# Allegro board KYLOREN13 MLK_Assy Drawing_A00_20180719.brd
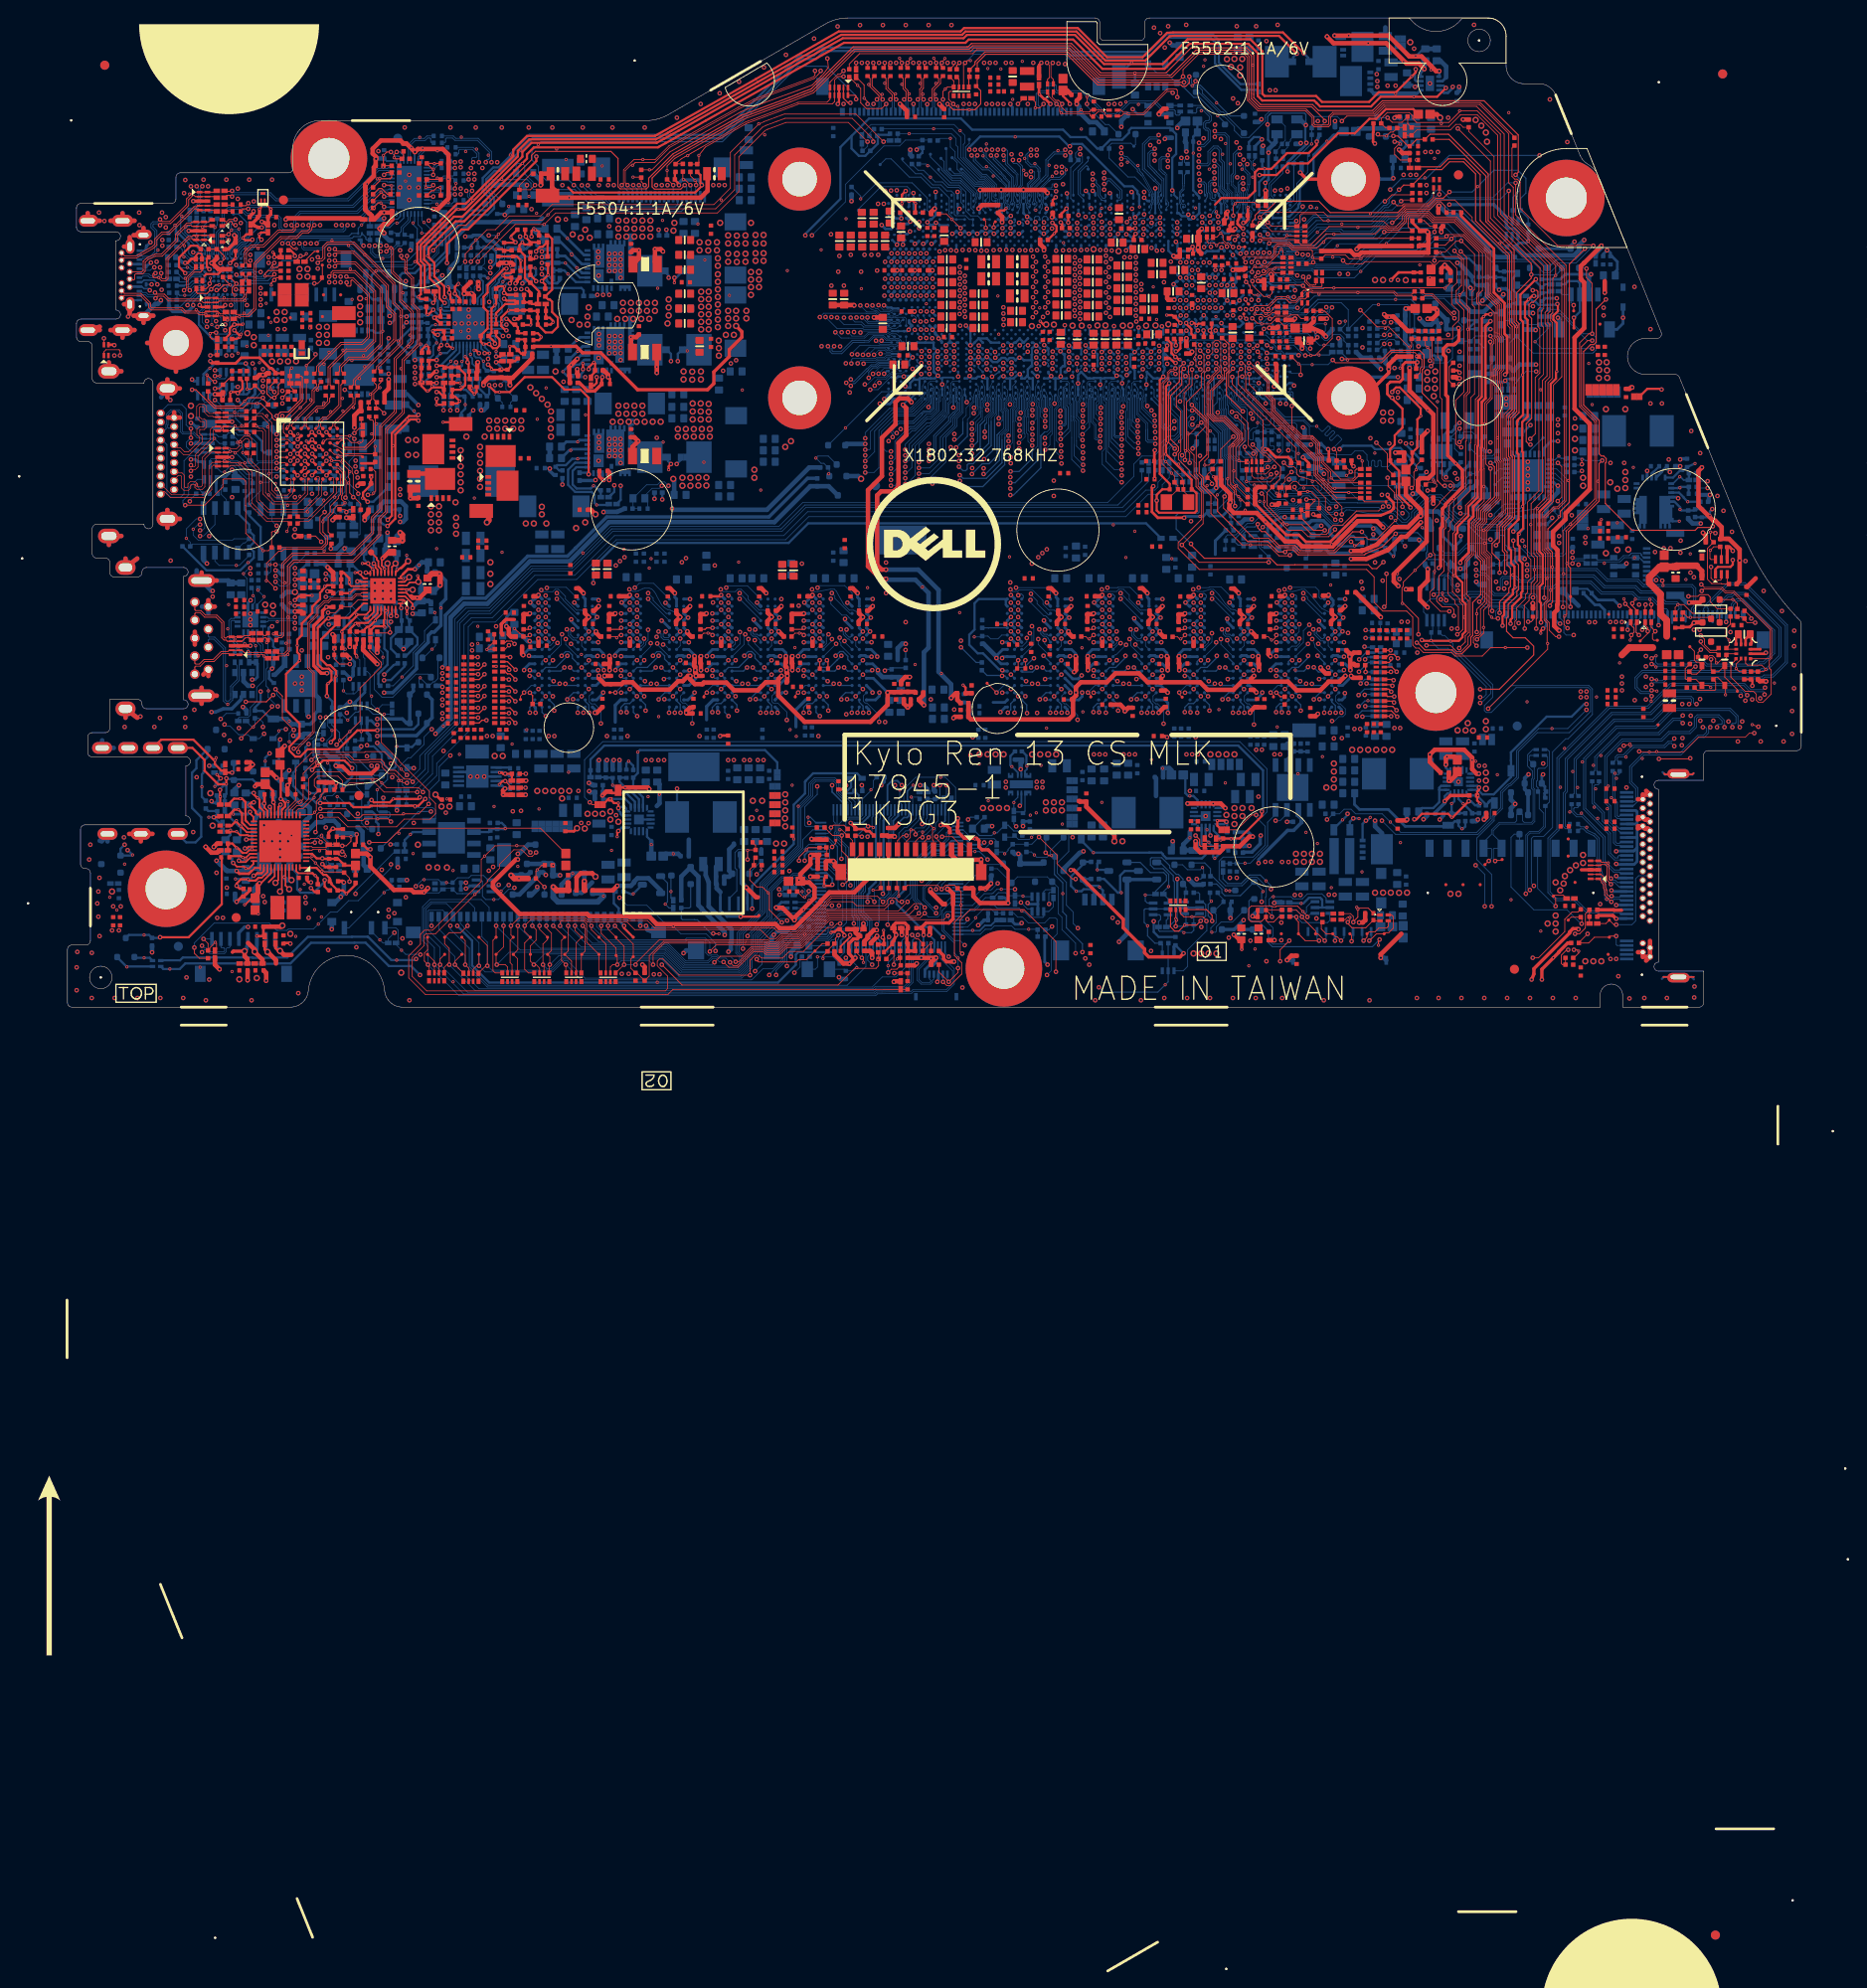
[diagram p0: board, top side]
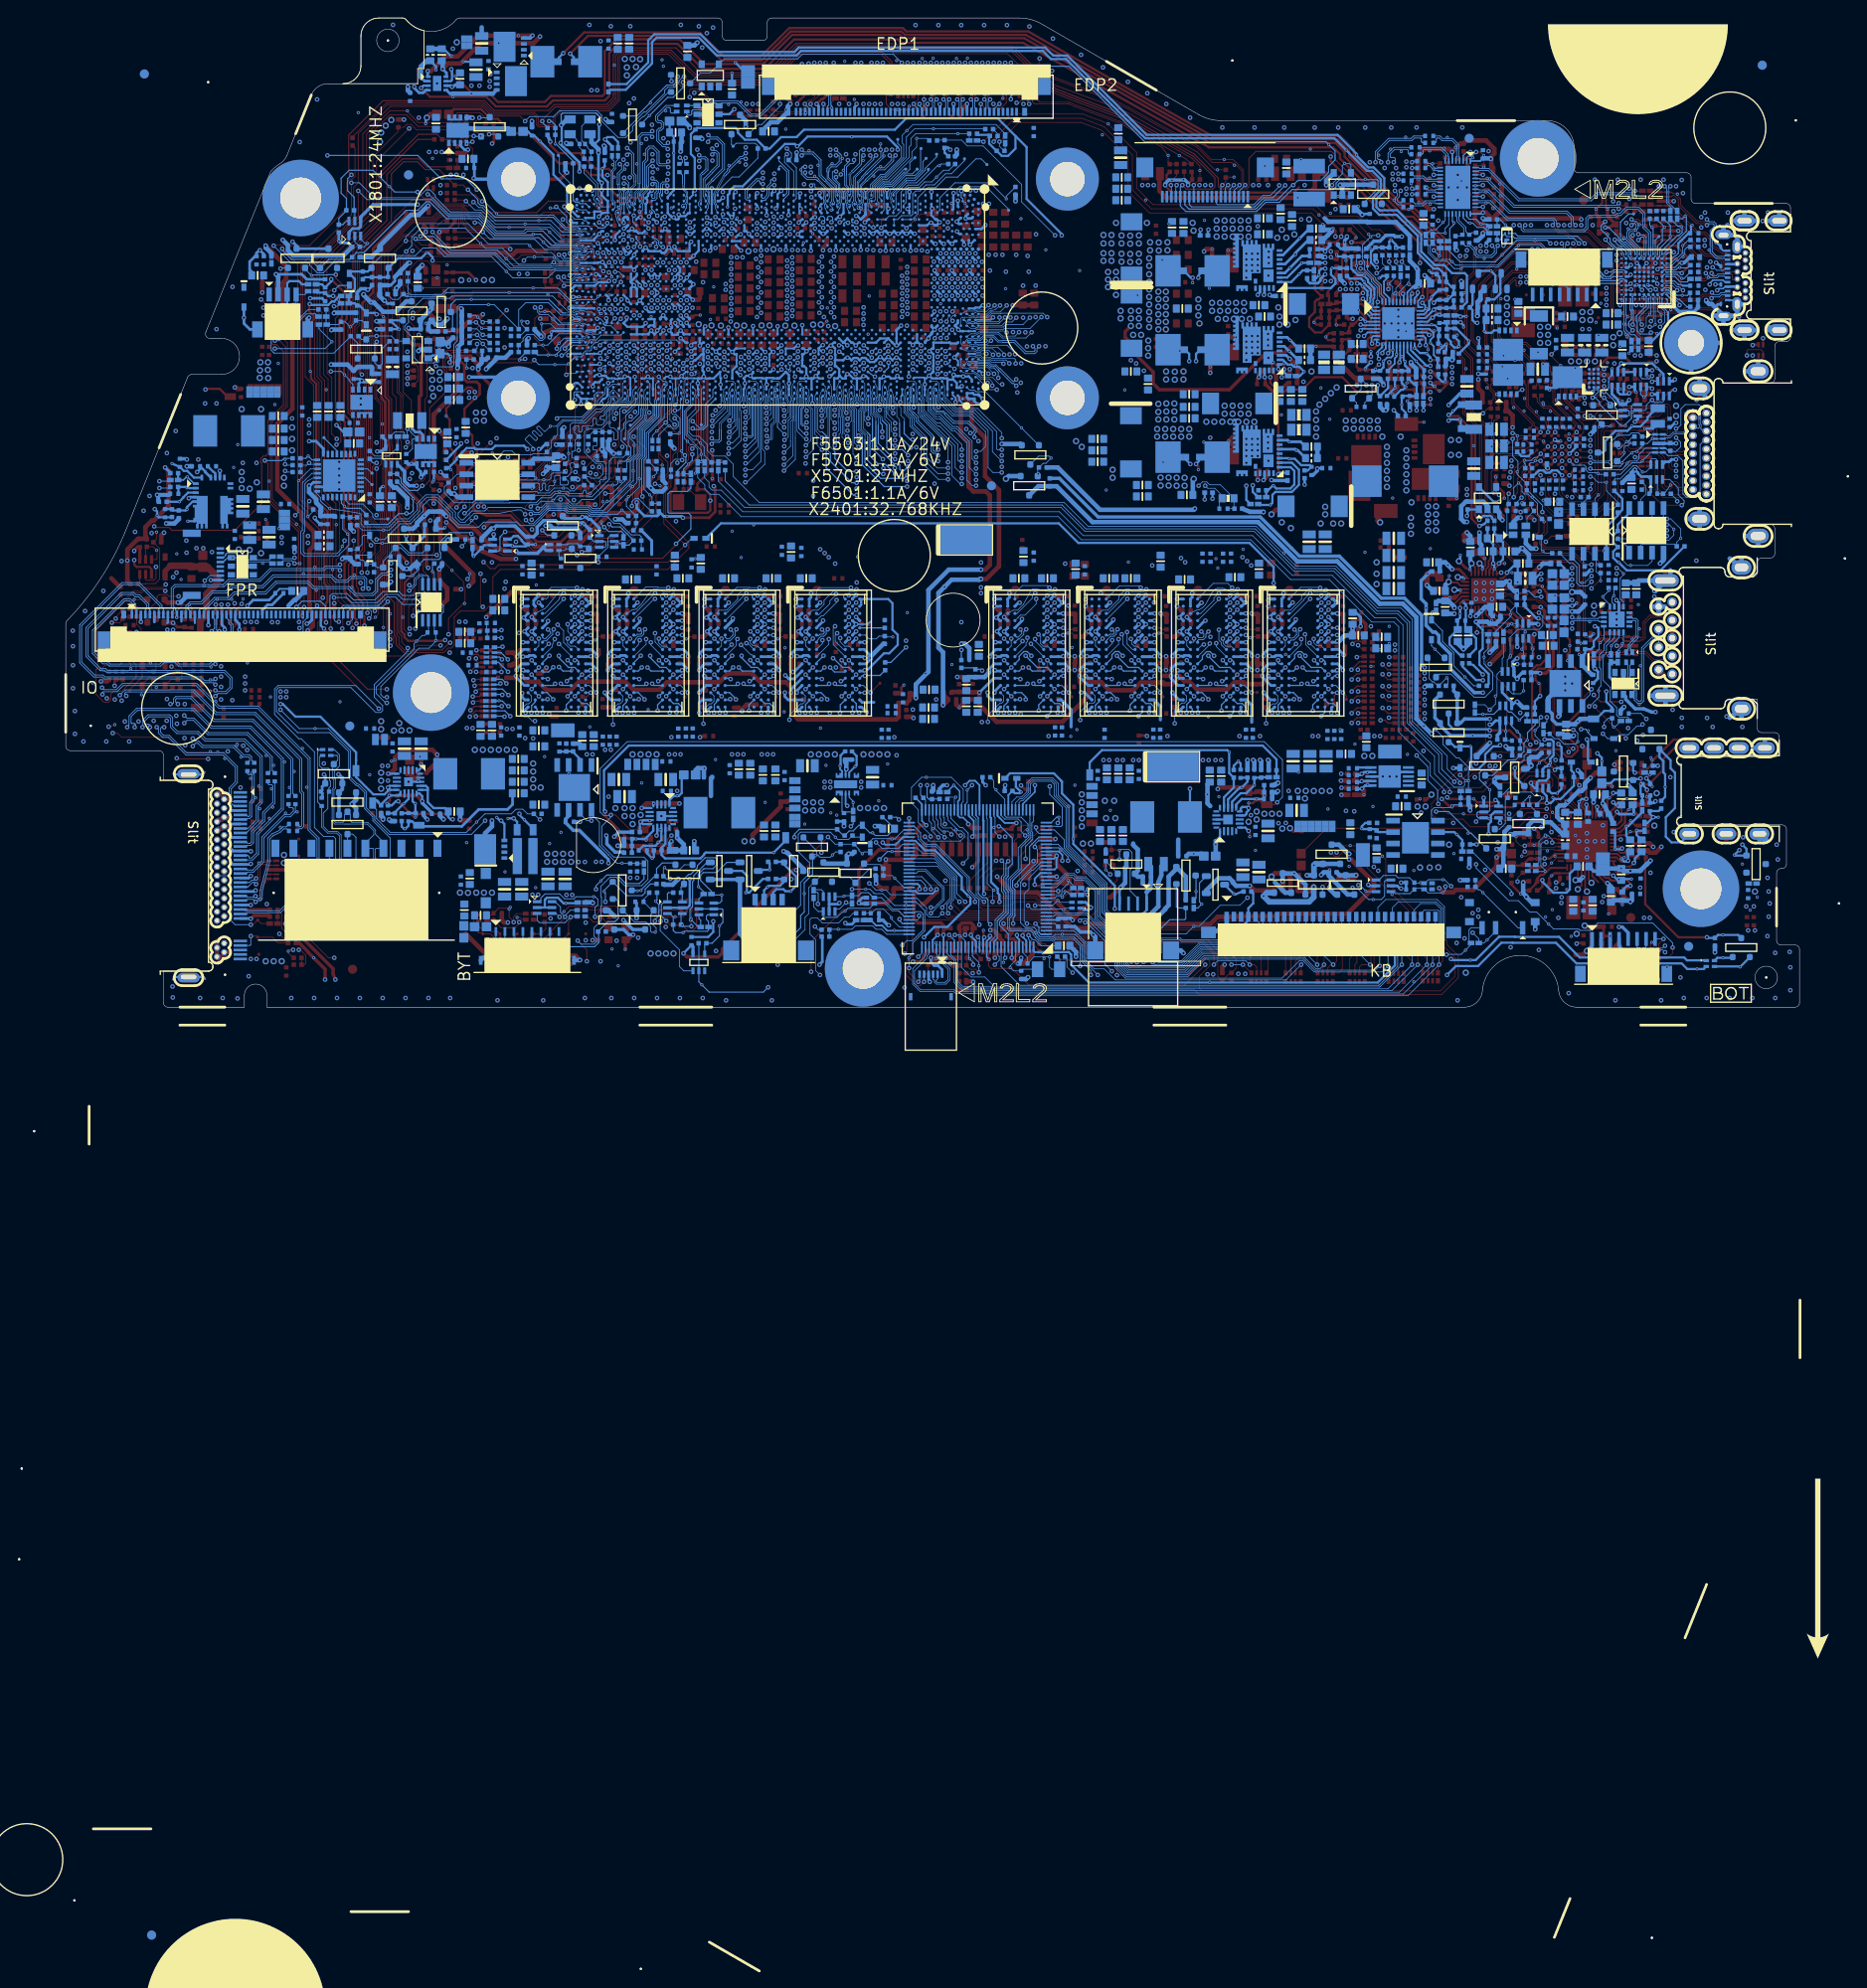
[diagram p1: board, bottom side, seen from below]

Outline 192.65 x 109.9 mm; copper layers: TOP, L2SGND, L3SGND, L4SGND, L5GND, L6, L7GND, BOTTOM. Coordinates in mm from the lower left corner of the outline.

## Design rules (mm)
constraint set DEFAULT: min track width 0.127, pair gap 0.102
net group CNV: nets CNV_RGI_DT CNV_WT_RCOMP
net group CPU_50: nets PROCHOT PROCHOT#_CPU
net group DDR4_4MIL: nets M_A_CLK M_B_CLK
net group DDR4_CKE_40-MW: nets M_A_CKE0 M_B_CKE0
net group DDR4_REST: nets SM_DRAMRST# SM_DRAMRST#_CPU
net group GND: nets EC_AGND MIC_GND
net group PAIR_CPU_DP1_CTRL_SMB-DIFF1: nets CPU_DP1_CTRL_CLK CPU_DP1_CTRL_DATA
net group PAIR_CPU_DP2_CTRL_SMB-DIFF1: nets CPU_DP2_CTRL_CLK CPU_DP2_CTRL_DATA
net group PAIR_CPU_I2C_TP-DIFF1: nets CPU_I2C_SCL_TP CPU_I2C_SDA_TP
net group PAIR_CPU_I2C_TS-DIFF1: nets CPU_I2C_SCL_TS CPU_I2C_SDA_TS
net group PAIR_CPU_SMB_THM-DIFF1: nets CPU_SMB_SCL_THM CPU_SMB_SDA_THM
net group PAIR_DMIC_CODEC_R-DIFF1: nets DMIC_SCL_CODEC_R DMIC_SDA_CODEC_R
net group PAIR_HDMI_SMB_CON-DIFF1: nets HDMI_SCL_CON HDMI_SDA_CON
net group PAIR_HDMI_SMB_R-DIFF1: nets HDMI_SCL_R HDMI_SDA_R
net group PAIR_I2C_PD_MUX-DIFF1: nets I2C_CLK_PD_MUX I2C_DATA_PD_MUX
net group PAIR_ICSP-DIFF1: nets ICSP_CLK ICSP_DAT
net group PAIR_KBC_PS2_I2C_TP-DIFF1: nets KBC_PS2_SCL_TP KBC_PS2_SDA_TP
net group PAIR_PCIE_RCOMP-DIFF1: nets PCIE_RCOMPN PCIE_RCOMPP
net group PAIR_PS175_SMB-DIFF1: nets PS175_CSCL PS175_CSDA
net group PAIR_SPK_I2C_CODEC-DIFF1: nets SPK_SCL_CODEC SPK_SDA_CODEC
net group PAIR_TYPEC_SMB-DIFF1: nets TYPEC_SMBCLK TYPEC_SMBDA
net group PAIR_TYPEC_SMB_Q-DIFF1: nets TYPEC_SMBCLK_Q TYPEC_SMBDA_Q
net group PAIR_VCORE_SENSE-DIFF1: nets VCCCORE_SENSE VSSCORE_SENSE
net group PAIR_VGT_SENSE-DIFF1: nets VCCGT_SENSE VSSGT_SENSE
net group PAIR_VSA_SENSE-DIFF1: nets VCCSA_SENSE VSSSA_SENSE
net group R72_16_M_A_CLK0-DIFF1: nets M_A_CLK0 M_A_CLK#0
net group R72_16_M_B_CLK0-DIFF1: nets M_B_CLK0 M_B_CLK#0
net group R85_12_USB1_USB30_RX-DIFF1: nets USB1_USB30_RX_N USB1_USB30_RX_P
net group R85_12_USB1_USB30_TX-DIFF1: nets USB1_USB30_TX_N USB1_USB30_TX_P
net group R85_15_CCD_USB20-DIFF1: nets CCD_USB20_N CCD_USB20_P
net group R85_15_CCD_USB20_CON-DIFF1: nets CCD_USB20_CON_N CCD_USB20_CON_P
net group R85_15_DP2_AUX_C2-DIFF1: nets DP2_AUX_C2_N DP2_AUX_C2_P
net group R85_15_TBTA_SENSE-DIFF1: nets TBTA_SENSEN TBTA_SENSEP
net group R85_15_USB2_USB20-DIFF1: nets USB2_USB20_N USB2_USB20_P
net group R85_15_USB4_USB20-DIFF1: nets USB4_USB20_N USB4_USB20_P
net group R85_15_WLAN_PCIE_RX-DIFF1: nets WLAN_PCIE_RX_N WLAN_PCIE_RX_P
net group R85_16_M_A_DQS0-DIFF1: nets M_A_DQS_DN0 M_A_DQS_DP0
net group R85_16_M_A_DQS1-DIFF1: nets M_A_DQS_DN1 M_A_DQS_DP1
net group R85_16_M_A_DQS2-DIFF1: nets M_A_DQS_DN2 M_A_DQS_DP2
net group R85_16_M_A_DQS3-DIFF1: nets M_A_DQS_DN3 M_A_DQS_DP3
net group R85_16_M_A_DQS4-DIFF1: nets M_A_DQS_DN4 M_A_DQS_DP4
net group R85_16_M_A_DQS5-DIFF1: nets M_A_DQS_DN5 M_A_DQS_DP5
net group R85_16_M_A_DQS6-DIFF1: nets M_A_DQS_DN6 M_A_DQS_DP6
net group R85_16_M_A_DQS7-DIFF1: nets M_A_DQS_DN7 M_A_DQS_DP7
net group R85_16_M_B_DQS0-DIFF1: nets M_B_DQS_DN0 M_B_DQS_DP0
net group R85_16_M_B_DQS1-DIFF1: nets M_B_DQS_DN1 M_B_DQS_DP1
net group R85_16_M_B_DQS2-DIFF1: nets M_B_DQS_DN2 M_B_DQS_DP2
net group R85_16_M_B_DQS3-DIFF1: nets M_B_DQS_DN3 M_B_DQS_DP3
net group R85_16_M_B_DQS4-DIFF1: nets M_B_DQS_DN4 M_B_DQS_DP4
net group R85_16_M_B_DQS5-DIFF1: nets M_B_DQS_DN5 M_B_DQS_DP5
net group R85_16_M_B_DQS6-DIFF1: nets M_B_DQS_DN6 M_B_DQS_DP6
net group R85_16_M_B_DQS7-DIFF1: nets M_B_DQS_DN7 M_B_DQS_DP7
net group SPI_CLK_50: nets SPI_CLK_HDMI SPI_CLK_PD
net group T8: nets CMP_VIN0_R VD_IN1_C
net group TESTPD_4MIL: nets CPU_D4_TP CPU_D6_TP
net group TPM_5MIL: nets TPM_GPIO0 TPM_GPIO4
net group USB_OC: nets USB_OC0# USB_OC1#
net group XTAL-MW: nets MEC_XTAL1_R MEC_XTAL2
net group 65982DC: nets 65982D_DBG_CTL1 65982D_DBG_CTL2 65982D_DEBUG1 65982D_DEBUG2 65982D_DIG_AUD_N 65982D_DIG_AUD_P 65982D_GPIO2 65982D_GPIO3 65982D_GPIO5 65982D_GPIO8 65982D_HPD_CON 65982D_HRESET 65982D_I2C_ADDR 65982D_LSRX 65982D_LSTX 65982D_MRESET 65982D_RESET_N 65982D_ROSC 65982D_SBU1_R 65982D_SBU2_R 65982D_UART_RX CAD_SNK DP1_HPD_CPU DP1_HPD_CPU_R DPEQ0_A1 DPEQ1 EQ0 EQ1 HPDIN I2CEN LPS_SW LPS_SW_A LPS_SW_B LPS_SW_C LPS_SW_D MUX_HPD_CON PD_IRQ1 PD_OVP_TRIP_P1 PD_VBUS_C_EN# PD_VBUS_C_EN_A PQ4417_D PQ4418_2 PQ4418_3 PQ4418_5 PQ4418_6 SSEQ0_A0 SSEQ1 TP_65982D_RESET_N UPD1_ALERT UPD1_ALERT_R USB1_SBU1 USB1_SBU1_R USB1_SBU2 USB1_SBU2_R VBUS_P_CTRL VBUS_P_CTRL_R VCCPD_VBUS_ACK
net group AUDIO_12MIL: nets CPVEE
net group AUDIO_BEEP1_20MIL: nets AUD_SPK_L+_C AUD_SPK_L- AUD_SPK_L-_C AUD_SPK_R+_C AUD_SPK_R-_C
net group AUDIO_BEEP_10MIL: nets AUD_HP1_JACK_L1 AUD_HP1_JACK_L1_R AUD_HP1_JACK_R1 AUD_HP1_JACK_R1_R AUD_HPJD_N AUD_HPOUT_L AUD_HPOUT_R AUD_PC_BEEP_C AUD_PC_BEEP_R AUD_SENSE_A AUD_VREF CBN CBP HDA_SPKR_R JACK_PLUG JACK_PLUG_DET KBC_BEEP_R LINE1-L_C LINE1-L_R LINE1_L LINE1_R MIC2_VREFO_L MIC2_VREFO_R SPKR
net group AUDIO_DIGITAL_50-MWS: nets HDA_RST_N_CPU
net group CLK_50-MWS: nets SUS_CLK
net group COMP_20MIL: nets CFG_RCOMP EMMC_RCOMP SD_RCOMP XCLK_BIASREF
net group CPU_50-MWS: nets PQ4405_3 PROCHOT#_CPU_R PWR_CHG_PROCHOT# PWR_CHG_PROCHOT#_R
net group DDR4_A_DATA_50-MW: nets M_A_DQ0 M_A_DQ1 M_A_DQ2 M_A_DQ3 M_A_DQ4 M_A_DQ5 M_A_DQ6 M_A_DQ7 M_A_DQ8 M_A_DQ9 M_A_DQ10 M_A_DQ11 M_A_DQ12 M_A_DQ13 M_A_DQ14 M_A_DQ15 M_A_DQ16 M_A_DQ17 M_A_DQ18 M_A_DQ19 M_A_DQ20 M_A_DQ21 M_A_DQ22 M_A_DQ23 M_A_DQ24 M_A_DQ25 M_A_DQ26 M_A_DQ27 M_A_DQ28 M_A_DQ29 M_A_DQ30 M_A_DQ31 M_A_DQ32 M_A_DQ33 M_A_DQ34 M_A_DQ35 M_A_DQ36 M_A_DQ37 M_A_DQ38 M_A_DQ39 M_A_DQ40 M_A_DQ41 M_A_DQ42 M_A_DQ43 M_A_DQ44 M_A_DQ45 M_A_DQ46 M_A_DQ47 M_A_DQ48 M_A_DQ49 M_A_DQ50 M_A_DQ51 M_A_DQ52 M_A_DQ53 M_A_DQ54 M_A_DQ55 M_A_DQ56 M_A_DQ57 M_A_DQ58 M_A_DQ59 M_A_DQ60 M_A_DQ61 M_A_DQ62 M_A_DQ63
net group DDR4_B_DATA_50-MW: nets M_B_DQ0 M_B_DQ1 M_B_DQ2 M_B_DQ3 M_B_DQ4 M_B_DQ5 M_B_DQ6 M_B_DQ7 M_B_DQ8 M_B_DQ9 M_B_DQ10 M_B_DQ11 M_B_DQ12 M_B_DQ13 M_B_DQ14 M_B_DQ15 M_B_DQ16 M_B_DQ17 M_B_DQ18 M_B_DQ19 M_B_DQ20 M_B_DQ21 M_B_DQ22 M_B_DQ23 M_B_DQ24 M_B_DQ25 M_B_DQ26 M_B_DQ27 M_B_DQ28 M_B_DQ29 M_B_DQ30 M_B_DQ31 M_B_DQ32 M_B_DQ33 M_B_DQ34 M_B_DQ35 M_B_DQ36 M_B_DQ37 M_B_DQ38 M_B_DQ39 M_B_DQ40 M_B_DQ41 M_B_DQ42 M_B_DQ43 M_B_DQ44 M_B_DQ45 M_B_DQ46 M_B_DQ47 M_B_DQ48 M_B_DQ49 M_B_DQ50 M_B_DQ51 M_B_DQ52 M_B_DQ53 M_B_DQ54 M_B_DQ55 M_B_DQ56 M_B_DQ57 M_B_DQ58 M_B_DQ59 M_B_DQ60 M_B_DQ61 M_B_DQ62 M_B_DQ63
net group DDR4_BA_40-MW: nets M_A_BA0 M_A_BA1 M_B_BA0 M_B_BA1
net group DDR4_BG_40-MW: nets M_A_BG0 M_A_BG1 M_A_BG1_E9_1 M_A_BG1_E9_2 M_A_BG1_E9_3 M_A_BG1_E9_4 M_A_BG1_M9_R M_B_BG0 M_B_BG1 M_B_BG1_E9_1 M_B_BG1_E9_2 M_B_BG1_E9_3 M_B_BG1_E9_4 M_B_BG1_M9_R
net group DDR4_CMD_40-MW: nets M_A_A0 M_A_A1 M_A_A2 M_A_A3 M_A_A4 M_A_A5 M_A_A6 M_A_A7 M_A_A8 M_A_A9 M_A_A10 M_A_A11 M_A_A12 M_A_A13 M_A_A14 M_A_A15 M_A_A16 M_A_ACT_N M_A_ALERT_N M_A_PARITY M_B_A0 M_B_A1 M_B_A2 M_B_A3 M_B_A4 M_B_A5 M_B_A6 M_B_A7 M_B_A8 M_B_A9 M_B_A10 M_B_A11 M_B_A12 M_B_A13 M_B_A14 M_B_A15 M_B_A16 M_B_ACT_N M_B_ALERT_N M_B_PARITY
net group DDR4_ODT10-MW: nets M_A_CS#0 M_A_ODT0 M_B_CS#0 M_B_ODT0
net group DDR4_VREF_20: nets M_VREF_CA_DIMMA M_VREF_CA_DIMMB V_SM_VREF_CNTA V_SM_VREF_CNTB
net group DDR4_VREF_40: nets DDR_VREF_S3
net group ESPI_50: nets ESPI_ALERT#
net group FAN_TACH: nets BEEP FAN1_PWM FAN1_TACH FAN_TACH1 FAN_TACH1_C
net group HDMI_DDI_TX_ALS_N0: nets HDMI_DDI_TX_N0
net group HDMI_DDI_TX_ALS_N1: nets HDMI_DDI_TX_N1
net group HDMI_DDI_TX_ALS_N2: nets HDMI_DDI_TX_N2
net group HDMI_DDI_TX_ALS_N3: nets HDMI_DDI_TX_N3
net group HDMI_DDI_TX_ALS_P0: nets HDMI_DDI_TX_P0
net group HDMI_DDI_TX_ALS_P1: nets HDMI_DDI_TX_P1
net group HDMI_DDI_TX_ALS_P2: nets HDMI_DDI_TX_P2
net group HDMI_DDI_TX_ALS_P3: nets HDMI_DDI_TX_P3
net group KBC: nets KSI0 KSI1 KSI2 KSI3 KSI4 KSI5 KSI6 KSI7 KSO0 KSO1 KSO2 KSO3 KSO4 KSO5 KSO6 KSO7 KSO8 KSO9 KSO10 KSO11 KSO12 KSO13 KSO14 KSO15 KSO16
net group LCD_BKLT: nets BKLT_CTRL L_BKLT_CTRL LCD_BRIGHTNESS
net group LED: nets BAT1_LED# BAT2_LED# BATT_WHITE_LED# BATT_WHITE_LED_R# CAP_LED# CAP_LED#_R CAP_LED_R# CHG_AMBER_LED# CHG_AMBER_LED_R# M2_PCIE_LED# MASK_BASE_LEDS# PCH_SATA_LED# SATA_PCIE_LED# SYS_LED_MASK# SYS_LED_MASK#_R
net group LED_10MIL: nets AMBER_LED_BAT BAT_AMBER BAT_WHITE CAP_LED CAP_LED_Q WHITE_LED_BAT
net group OTHER-4MIL: nets 1D8V_EN# 1D8V_EN_R# 3D3V_LDO_SET 3V_5V_DSW_OK AC_PRESENT AD_IA AUX_EN_WOWL AUX_EN_WOWL_R BKLT_IN_EC BLON_OUT_C BLUETOOTH_EN BLUETOOTH_EN_R BOARD_ID BOARD_ID1 BOARD_ID2 CARD_CLKREQ_CPU_N CATERR#_CPU CHGR_PSYS_IMVP CLK_PCIE_PEG_REQ0_N CLK_PCIE_PEG_REQ2_N CLK_PCIE_PEG_REQ5_N CPU_DP_HPD_P CPU_SMB_ALERT# CPU_SMB_ALERT#_P0 CPU_SMB_ALERT#_P1 CTL2 CTL3 DBC_EN_R DBC_PANEL_EN DVSS EDP_HPD_CON EDP_HPD_CPU FAN_PWM1_C FFS_INT1 FFS_INT2 FPR_SCAN# GPD11/LANPHYPC GPD_7 GPP_B22_GSPI1_MOSI GPP_E0/SATAXPCIE0/SATAGP0 GPP_E1/SATAXPCIE1/SATAGP1 GPP_E3/CPU_GP0 GPP_E23_STRAP GPP_H17_STRAP GPP_H21 GPP_H23 GSEN2_INT1 GSEN2_INT1_C GSEN2_INT1_ISH GSEN2_INT2 GSEN2_INT2_C GSEN2_INT2_ISH GSEN_INT1 GSEN_INT2 GSENSOR_CS GSENSOR_SDO GYRO_DRDY_ISH GYRO_INT GYRO_INT_C GYRO_INT_ISH HDMI_CEC HDMI_CEC_CON HDMI_CEC_R HDMI_HPD_ALS HDMI_HPD_CON HDMI_HPD_CPU HOST_DEBUG_TX HOST_DEBUG_TX_CON I_ADP ICSP_CLR ILIM_HI ILIM_LO ILIM_SEL INPUT3VSEL IST_TRIG KB_DISABLE_CPU_R KB_LED_BL_DET KB_LED_DET_C KB_LED_PWM KBC_PWRBTN# L_BKLT_EN L_BKLT_EN_R LCD_TST_C M2_SSD_PEDET MASK_SATA_LED# MCDP2800_D8 MCDP2800_UART_TX ME_FWP ME_FWP_EC MEM_CONFIG0 MEM_CONFIG1 MEM_CONFIG2 MEM_CONFIG3 MEM_CONFIG4 MESW1_B MODEL_ID MSATA_DEVSLP_R NB_MODE# NB_MUTE# NC_HDMI_RE_DRIVER_F7 NC_SIO_SLP_S4#_EC NC_U3_PD#_EC NRB_BIT PBAT_PRES1# PBAT_PRES# PCH_BATLOW# PCIE_WAKE# PD4403_A PD4403_K PIRQA# PROJECT_ID0 PROJECT_ID1 PROJECT_ID2 PROJECT_ID3 PS175_CEC_EN PS175_PD# PS175_RST# PS_ID_R PS_ID_R1 Q502_G Q5705_2 Q5705_5_6 REXT REXT_R RTC_3P3_EN_G SIO_EXT_SMI# SIO_EXT_WAKE# SIO_PWRBTN# SKTOCC# SM_INTRUDER# SPK_DET#_CON SPK_ID SSD_CLKREQ_CPU_N SSD_DEVSLP SSD_SCP# SSD_SCP#_1 SYS_PRES1# SYSPWR_PRES TEST_MODE_1 TEST_MODE_2 TEST_MODE_3 TEST_MODE_4 TEST_MODE_5 TEST_MODE_6 TEST_MODE_7 TEST_MODE_8 THERMTRIP#_CPU TOUCH_DETECT TOUCH_DETECT_R TP_TPM_GPIO1 TP_TPM_GPIO3 TP_TPM_PP TP_WAKE_KBC# TPM_ID TPM_SPI_IRQ# TYPEC_DCIN1_EN# U3_PD#_EC USB2_ID USB2_VBUSSENSE USB_OC2# USB_OC3# USB_POWERSHARE_VBUS_EN USB_PWR_EN# USB_PWR_SHR_EN# USB_PWR_SHR_EN_L# V0.85A_VID0 V0.85A_VID1 VCCDSW_ON VCREF0 VR_RDY VRALERT# VRAM_ID1 VRAM_ID2 WIFI_RF_EN WIFI_RF_EN_R WLAN_CLKREQ_CPU_N WLAN_EN# WLAN_EN_R#
net group PECI_SVID: nets PECI_CPU
net group PECI_SVID-MW: nets H_PECI
net group PLATFORM: nets 1D0V_S5_PWRGD 1D2V_HDMI_EN 1D2V_HDMI_EN_R 1D8V_S5_EN 2D5V_S3_EN 2D5V_S3_PWRGD 3V_5V_PWRGD +SDC_IN_SW +SDC_IN_SW_R1 A_ZQ_RAM1 A_ZQ_RAM2 A_ZQ_RAM3 A_ZQ_RAM4 B_ZQ_RAM1 B_ZQ_RAM2 B_ZQ_RAM3 B_ZQ_RAM4 CLKRUN# EDP_VDD_EN GYRO_DRDY H_CPUPWRGD IC_DELAY IR_CAM_DET# IR_CAMERA_DET#_R ISH_KB_DISABLE ITP_PMODE KB_DET# LAN_WAKE# LCD_TST LCD_VCC_TEST_EN LID_CL_SIO# LID_CL_SIO_TAB# LVDS_VDD_EN_R ME_SUS_PWR_ACK_R MEM_CHA_EN MEM_CHB_EN NCT7718_DXN NCT7718_DXP PCH_PLTRST# PCH_RSMRST# PCIE_WAKE#_CPU PM_RSMRST#_M POWER_SW_IN# PQ4405_2 PQ4405_5 PQ4405_6 PQ4408_C PQ4408_E PRIM_PWRGD PTP_DIS# RSMRST_PWRGD# RTCRST_ON SM_PGCNTL SRTC_RST# SUSACK#_R TP_ON#_GATE VCCSTG_EN_L1 VCCSTG_EN_R1 VCCSTU_EN_R VR_EN
net group POWER_10M: nets 1D0V_S5_EN 1D0V_VCCA_XTAL 1D0V_VCCAMPHYPLL 1D0V_VCCDSW 1D24V_VCCDPHY 1D24V_VCCDPHY_EC 1V_VCCST_CPU 1V_VCCSTG 3D3V_1D8V_AVDD_IO 3D3V_RTC_SYS 3D3V_TBT 3D3V_VCCPRTC 3V5V_CT1 3V5V_CT2 5V_S5_EN 65982D_BUSPWR 65982D_GND 65982D_LDO_1V8A 65982D_LDO_1V8D 65982D_LDO_BMC AC_DIS AC_IN# AUDIO_47 AUX_MODE BREATH_LED# DC_IN_OFF HDMI_BOM_OPTION HVA_GATE1 HVA_GATE2 HW_ACAV_IN HW_ACAVIN_NB I_BATT LDO1_CAP LDO2_CAP LDO3_CAP MIC_CAP PD_VBUS_C_CTRL1 PD_VBUS_C_CTRL1_A PD_VBUS_C_CTRL1_R PRD_CC1 PRD_CC2 PU4348_G PWR_0D6V_S3EN PWR_0D6V_S5EN PWR_1D0V_BT PWR_1D0V_FB_A PWR_1D0V_PFM PWR_1D0V_PG PWR_1D0V_SS PWR_1D0V_TON PWR_3D3V_FB PWR_3D3V_VOUT PWR_5V_FB PWR_5V_FB_A PWR_5V_VOUT PWR_CHG_ACIN PWR_CHG_ACOK PWR_CHG_AIN PWR_CHG_AMON PWR_CHG_ASGATE PWR_CHG_BATGONE PWR_CHG_BGATE PWR_CHG_COMP PWR_CHG_COMP_R PWR_CHG_CSIN PWR_CHG_CSIN_R PWR_CHG_CSIP PWR_CHG_CSIP_R PWR_CHG_CSON PWR_CHG_CSON_R PWR_CHG_CSOP PWR_CHG_CSOP_R PWR_CHG_DCIN PWR_CHG_DCIN_R PWR_CHG_OTGEN PWR_CHG_OTGPG PWR_CHG_PROG PWR_VCCGT_COMP PWR_VCCGT_COMP1 PWR_VCCGT_FB PWR_VCCGT_FB1 PWR_VCCGT_FB2 PWR_VCCGT_FB_RC PWR_VCCGT_FCCM# PWR_VCCGT_FCCM#_RA PWR_VCCGT_FCCM#_RB PWR_VCCGT_IMON PWR_VCCGT_ISEN1 PWR_VCCGT_ISEN2 PWR_VCCGT_ISUMN PWR_VCCGT_ISUMN_GA PWR_VCCGT_ISUMN_GB PWR_VCCGT_ISUMN_P_1 PWR_VCCGT_ISUMN_P_2 PWR_VCCGT_ISUMN_RC PWR_VCCGT_ISUMNB PWR_VCCGT_ISUMP PWR_VCCGT_ISUMP_GA PWR_VCCGT_ISUMP_GB PWR_VCCGT_NTC PWR_VCCGT_NTC1 PWR_VCCGT_PWMA PWR_VCCGT_PWMA_RA PWR_VCCGT_PWMB PWR_VCCGT_PWMB_RA PWR_VCCGT_RTN PWR_VCCSA_COMP PWR_VCCSA_COMP_RC PWR_VCCSA_FB PWR_VCCSA_FB1 PWR_VCCSA_FB2 PWR_VCCSA_FB_RC PWR_VCCSA_FCCM PWR_VCCSA_IMON PWR_VCCSA_ISUMN PWR_VCCSA_ISUMN_P_1 PWR_VCCSA_ISUMN_P_2 PWR_VCCSA_ISUMN_R PWR_VCCSA_ISUMN_RC PWR_VCCSA_ISUMNB PWR_VCCSA_ISUMP PWR_VCCSA_ISUMP_R PWR_VCCSA_RTN PWR_VCORE_COMP PWR_VCORE_COMP1 PWR_VCORE_FB PWR_VCORE_FB1 PWR_VCORE_FB2 PWR_VCORE_FB_RC PWR_VCORE_FCCM# PWR_VCORE_FCCM#_R PWR_VCORE_IMON PWR_VCORE_ISUMN PWR_VCORE_ISUMN_G PWR_VCORE_ISUMN_P_1 PWR_VCORE_ISUMN_P_2 PWR_VCORE_ISUMN_RC PWR_VCORE_ISUMNA PWR_VCORE_ISUMP PWR_VCORE_ISUMP_G PWR_VCORE_NTC PWR_VCORE_NTC1 PWR_VCORE_PROG1 PWR_VCORE_PROG2 PWR_VCORE_PWM_R PWR_VCORE_RTN PWR_VCORE_VCC_R PWR_VCORE_VRHOT# PWR_VDDQ_FB_A PWR_VDDQ_ILMT PWR_VDDQ_PG PWR_VDDQ_VCC Q6204_G VCCRTCEXT VCCST_PWRGD VCCST_PWRGD_R VCI_IN1# VDDQ_EN VDDQ_PWRGD
net group POWER_10M_POWER: nets 1.8V_RUN_FB 3V_5V_POK# 3V_5V_POK_C AC_IN#_G AD_OFF_L AD_OFF_R PWR_1D0V_FB PWR_1D8V_POK PWR_2D5V_FB PWR_3D3V_EN PWR_3D3V_FB2 PWR_3V_PG PWR_5V_EN PWR_5V_EN1_R PWR_5V_PG PWR_VCCSA_PWM PWR_VCORE_PWM PWR_VDDQ_FB
net group POWER_15M: nets Q6205_Q USB1_CC1 USB1_CC2
net group POWER_20M: nets 1D8V_S0 1D8V_S5_KBC 1V_VREF_CPU 3D3V_AUX_S5 3D3V_ECVBAT 3D3V_RTC 5V_AUX_S5 +5V_AVDD +RTC_VCC +V_VREF_PATH1 +V_VREF_PATH2 PQ4348_D PWR_3D3V_BOOT PWR_3D3V_BOOT_A PWR_5V_BOOT PWR_5V_BOOT_A PWR_CHG_BOOT1 PWR_CHG_BOOT2 PWR_CHG_SNB PWR_CHG_VDDP RTC_3P3_EN_D RTC_AUX_S5 TCH_PNL_3D3V_5V VTT_CNTL
net group POWER_20M_POWER: nets 1D8V_CPVDD 5V_KB_BL KB_BL_CTRL# PWR_0D6V_VTT_CNTL PWR_VCCGT_BOOTA PWR_VCCGT_BOOTA_RC PWR_VCCGT_BOOTB PWR_VCCGT_BOOTB_RC PWR_VCCGT_SNB1 PWR_VCCGT_SNB2 PWR_VCCGT_VCCDA PWR_VCCGT_VCCDB PWR_VCCSA_BST PWR_VCCSA_BST_RC PWR_VCORE_BOOT PWR_VCORE_BOOT_RC PWR_VCORE_SNB PWR_VCORE_VCC PWR_VDDQ_BOOT
net group POWER_25M: nets PQ4302_B PS_ID PSID_DISABLE#_R_C
net group POWER_25M_POWER: nets PWR_CHG_BT1_R PWR_CHG_BT2_R PWR_CHG_UGATE2 PWR_VCCGT_BOOTRA PWR_VCCGT_BOOTRB PWR_VCORE_BOOTR PWR_VDDQ_BOOT_A
net group POWER_40M_POWER: nets PWR_VCCSA_DRVH PWR_VCCSA_DRVL PWR_VCORE_VIN
net group POWER_160M: nets VDD
net group POWER_320M_POWER: nets PWR_CHG_VBAT1
net group REF10M: nets VR_CAP
net group RESET_SIGNAL: nets 3V5V_S0_ON 3V_5V_EN ACOK# ALWON EXT_PWR_GATE# GPPC_H18_BOOTMPC GPPC_H18_VCCIO_LPM PANEL_BKEN PANEL_BKEN_EC PCH_DPWROK PLT_RST#_Q_TPM2 PLTRST#_CPU PM_PCH_PWROK PM_RSMRST# PM_SLP_S0# PM_SLP_S3# PM_SLP_S4# RESET_OUT# RTC_DET# RTC_RST# SYS_PWROK TCH_INTR# TOUCH_PANEL_INTR# TOUCH_PANEL_PD# TOUCH_REPORT_SW TP_EN#
net group SPI_50-MWS: nets SIO_EXT_SCI# SIO_RCIN# SPI_CS_HDMI SPI_CS_PD SPI_HOLD_HDMI SPI_HOLD_PD SPI_IRQ#_TPM2 SPI_SI_HDMI SPI_SI_PD SPI_SO_HDMI SPI_SO_PD SPI_WP_HDMI SPI_WP_PD
net group SSD_PCIE_TX_CON_N1: nets SSD_PCIE_TX_N1
net group SSD_PCIE_TX_CON_N2: nets SSD_PCIE_TX_N2
net group SSD_PCIE_TX_CON_N3: nets SSD_PCIE_TX_N3
net group SSD_PCIE_TX_CON_P1: nets SSD_PCIE_TX_P1
net group SSD_PCIE_TX_CON_P2: nets SSD_PCIE_TX_P2
net group SSD_PCIE_TX_CON_P3: nets SSD_PCIE_TX_P3
net group SSD_SATA_TX_CON_N: nets SSD_SATA_TX_N
net group SSD_SATA_TX_CON_P: nets SSD_SATA_TX_P
net group SVID-MW: nets SVID_ALERT#_CPU SVID_ALERT#_CPU_R SVID_ALERT#_VR SVID_CLK_CPU SVID_CLK_CPU_R SVID_CLK_VR SVID_DATA_CPU SVID_DATA_CPU_R SVID_DATA_VR
net group T8-MW: nets CMP_VOUT0
net group THERM_SHUTDOWN: nets ALERT# PURE_HW_SHUTDOWN# T_CRIT# THERM_SYS_SHDN#
net group UART_MW-MW: nets UART_2_CRXD_DTXD UART_2_CRXD_DTXD_CON UART_2_CTXD_DRXD UART_2_CTXD_DRXD_CON
net group XDP_CHECK: nets BPM_CPU_N0 BPM_CPU_N1 BPM_CPU_N2 BPM_CPU_N3 CFG3 CFG4 PCH_JTAG_TCK XDP_DBRESET# XDP_PRDY# XDP_PREQ# XDP_TCLK XDP_TDI XDP_TDO_CPU XDP_TMS XDP_TRST#
net group XTAL_NO_TP: nets XTL_27M_X1_HDMI XTL_27M_X2_C XTL_27M_X2_HDMI XTL_27M_X2_R

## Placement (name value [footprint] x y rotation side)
AFTP2601  AFTE14P-GP  [AFTE14P-75]  167.39 75.46 270 top
AFTP2602  AFTE14P-GP  [AFTE14P-75]  167.36 77.36 270 top
AFTP2603  AFTE14P-GP  [AFTE14P-75]  170.81 80.66 270 top
AFTP2604  AFTE14P-GP  [AFTE14P-75]  170.28 75.89 270 top
AFTP2901  AFTE14P-GP  [AFTE14P-75]  23.16 4.84 0 top
AFTP2902  AFTE14P-GP  [AFTE14P-75]  24.89 5.81 0 top
AFTP2903  AFTE14P-GP  [AFTE14P-75]  18.34 6.11 270 top
AFTP2904  AFTE14P-GP  [AFTE14P-75]  20.07 7.13 270 top
AFTP4301  AFTE14P-GP  [AFTE14P-75]  22.35 76.6 180 top
AFTP4302  AFTE14P-GP  [AFTE14P-75]  24.77 76.6 180 top
AFTP4303  AFTE14P-GP  [AFTE14P-75]  28.45 79.14 180 top
AFTP4304  AFTE14P-GP  [AFTE14P-75]  28.32 82.44 180 top
AFTP4305  AFTE14P-GP  [AFTE14P-75]  30.35 79.14 180 top
AFTP4306  AFTE14P-GP  [AFTE14P-75]  166.75 16.78 0 top
AFTP4307  AFTE14P-GP  [AFTE14P-75]  166.75 18.69 0 top
AFTP4308  AFTE14P-GP  [AFTE14P-75]  167.51 13.86 0 top
AFTP4309  AFTE14P-GP  [AFTE14P-75]  166.75 9.67 0 top
AFTP4310  AFTE14P-GP  [AFTE14P-75]  159.41 16.4 0 top
AFTP4311  AFTE14P-GP  [AFTE14P-75]  157.51 15.84 0 top
AFTP4312  AFTE14P-GP  [AFTE14P-75]  155.07 13.61 0 top
AFTP4313  AFTE14P-GP  [AFTE14P-75]  156.97 13.61 0 top
AFTP4314  AFTE14P-GP  [AFTE14P-75]  153.16 13.61 0 top
AFTP4315  AFTE14P-GP  [AFTE14P-75]  165.1 12.34 0 top
AFTP4316  AFTE14P-GP  [AFTE14P-75]  28.32 76.73 0 top
AFTP5701  AFTE14P-GP  [AFTE14P-75]  32.79 61.13 0 top
AFTP6108  AFTE14P-GP  [AFTE14P-75]  167 45.61 0 top
AFTP6109  AFTE14P-GP  [AFTE14P-75]  146.51 56.15 90 top
AFTP6110  AFTE14P-GP  [AFTE14P-75]  185.55 35.1 180 top
AFTP6111  AFTE14P-GP  [AFTE14P-75]  176.66 40.76 0 top
AFTP6112  AFTE14P-GP  [AFTE14P-75]  180.26 40.05 180 top
AFTP6113  AFTE14P-GP  [AFTE14P-75]  178.56 40.91 0 top
AFTP6114  AFTE14P-GP  [AFTE14P-75]  174.75 40.68 0 top
AFTP6301  AFTE14P-GP  [AFTE14P-75]  171.32 9.67 0 top
AFTP6303  AFTE14P-GP  [AFTE14P-75]  171.32 7.77 0 top
AFTP6304  AFTE14P-GP  [AFTE14P-75]  171.2 5.86 0 top
AFTP6501  AFTE14P-GP  [AFTE14P-75]  40.01 5.86 0 top
AFTP6502  AFTE14P-GP  [AFTE14P-75]  43.81 7.77 0 top
AFTP6503  AFTE14P-GP  [AFTE14P-75]  43.81 5.86 0 top
AFTP6504  AFTE14P-GP  [AFTE14P-75]  62.87 5.61 0 top
AFTP6505  AFTE14P-GP  [AFTE14P-75]  41.91 5.86 0 top
AFTP6506  AFTE14P-GP  [AFTE14P-75]  41.91 7.77 0 top
AFTP6507  AFTE14P-GP  [AFTE14P-75]  55.24 7.77 0 top
AFTP6508  AFTE14P-GP  [AFTE14P-75]  45.72 5.86 0 top
AFTP6509  AFTE14P-GP  [AFTE14P-75]  45.72 7.77 0 top
AFTP6510  AFTE14P-GP  [AFTE14P-75]  47.62 7.77 0 top
AFTP6511  AFTE14P-GP  [AFTE14P-75]  53.34 7.77 0 top
AFTP6512  AFTE14P-GP  [AFTE14P-75]  40.01 7.77 0 top
AFTP6513  AFTE14P-GP  [AFTE14P-75]  53.34 5.86 0 top
AFTP6514  AFTE14P-GP  [AFTE14P-75]  47.62 5.86 0 top
AFTP6515  AFTE14P-GP  [AFTE14P-75]  49.53 7.77 0 top
AFTP6516  AFTE14P-GP  [AFTE14P-75]  51.44 7.77 0 top
AFTP6517  AFTE14P-GP  [AFTE14P-75]  49.53 5.86 0 top
AFTP6518  AFTE14P-GP  [AFTE14P-75]  51.44 5.86 0 top
AFTP6519  AFTE14P-GP  [AFTE14P-75]  59.05 5.86 0 top
AFTP6520  AFTE14P-GP  [AFTE14P-75]  57.15 5.86 0 top
AFTP6521  AFTE14P-GP  [AFTE14P-75]  59.05 7.77 0 top
AFTP6522  AFTE14P-GP  [AFTE14P-75]  60.96 5.73 0 top
AFTP6523  AFTE14P-GP  [AFTE14P-75]  60.96 7.77 0 top
AFTP6524  AFTE14P-GP  [AFTE14P-75]  57.15 7.77 0 top
AFTP6525  AFTE14P-GP  [AFTE14P-75]  148.21 8.15 0 top
AFTP6529  AFTE14P-GP  [AFTE14P-75]  76.83 10.18 180 top
AFTP6530  AFTE14P-GP  [AFTE14P-75]  76.71 12.21 180 top
AFTP6531  AFTE14P-GP  [AFTE14P-75]  134.87 8.15 0 top
AFTP6532  AFTE14P-GP  [AFTE14P-75]  146.3 8.15 270 top
AFTP6533  AFTE14P-GP  [AFTE14P-75]  144.4 8.15 270 top
AFTP6534  AFTE14P-GP  [AFTE14P-75]  138.68 8.15 180 top
AFTP6535  AFTE14P-GP  [AFTE14P-75]  136.78 8.15 180 top
AFTP6536  AFTE14P-GP  [AFTE14P-75]  140.59 8.15 0 top
AFTP6537  AFTE14P-GP  [AFTE14P-75]  142.49 8.15 0 top
AFTP6538  AFTE14P-GP  [AFTE14P-75]  62.87 7.77 0 top
AFTP6539  AFTE14P-GP  [AFTE14P-75]  55.24 5.86 0 top
AFTP6607  AFTE14P-GP  [AFTE14P-75]  176.73 31.36 0 top
AFTP6608  AFTE14P-GP  [AFTE14P-75]  171.25 43.66 0 top
AFTP6609  AFTE14P-GP  [AFTE14P-75]  83.06 6.24 0 top
BATT1  HIG-CON10-2-GP  [A2014WRA-SF-10PNLNG1NS1R]  160.35 12.7 180 bottom
BIOS1  W25Q128JVSIQ-GP  [SOIC8-1H86]  144.7 58.57 270 bottom
C501  SCD1U25V2KX-1-DL-GP  [C402H22]  135.38 56.41 0 top
C801  SC1U10V2KX-1DLGP  [C402H22]  122.68 97.05 0 bottom
C802  SC1U10V2KX-1DLGP  [C402H22]  109.47 88.74 180 top
C803  SC1U10V2KX-1DLGP  [C402H22]  122.09 72.54 180 top
C804  SC1U10V2KX-1DLGP  [C402H22]  120.98 51.17 90 top
C805  SCD1U25V2KX-1-DL-GP  [C402H22]  124.05 84.15 270 top
C806  SC1U10V2KX-1DLGP  [C402H22]  125.52 83.72 90 top
C1102  SC1U10V2KX-1DLGP  [C402H22]  97.83 74.45 90 top
C1103  SC1U10V2KX-1DLGP  [C402H22]  93.13 77.29 90 top
C1104  SC1U10V2KX-1DLGP  [C402H22]  91.23 81.86 90 top
C1105  SC1U10V2KX-1DLGP  [C402H22]  95.55 86.13 180 top
C1106  SC1U10V2KX-1DLGP  [C402H22]  95.14 81.86 90 top
C1107  SC1U10V2KX-1DLGP  [C402H22]  93.19 81.86 90 top
C1108  SC1U10V2KX-1DLGP  [C402H22]  118.99 74.12 0 top
C1109  SC1U10V2KX-1DLGP  [C402H22]  120.21 73.74 90 top
C1110  SC1U10V2KX-1DLGP  [C402H22]  109.14 74.57 0 top
C1111  SC1U10V2KX-1DLGP  [C402H22]  108.37 74.57 0 top
C1112  SC22U6D3V3MX-1-DL-GP  [C603H40]  123.49 81.9 270 top
C1113  SC22U6D3V3MX-1-DL-GP  [C603H40]  129.46 74.96 0 top
C1114  SC1U10V2KX-1DLGP  [C402H22]  124.96 78.66 0 top
C1115  SC22U6D3V3MX-1-DL-GP  [C603H40]  162.13 66.19 180 bottom
C1116  SC1U10V2KX-1DLGP  [C402H22]  149.61 81.17 180 top
C1117  SC1U10V2KX-1DLGP  [C402H22]  150.37 81.17 180 top
C1118  SC22U6D3V3MX-1-DL-GP  [C603H40]  163.45 66.19 180 bottom
C1119  SC1U10V2KX-1DLGP  [C402H22]  128.29 82.88 180 top
C1120  SC10U6D3V3MX-DL-GP  [C603H36]  164.72 66.19 180 bottom
C1121  SC1U10V2KX-1DLGP  [C402H22]  127.53 82.88 180 top
C1122  SC22U6D3V3MX-1-DL-GP  [C603H40]  128.95 79.32 270 top
C1123  SC10U6D3V3MX-DL-GP  [C603H36]  131.31 75.01 0 top
C1128  SC22U6D3V3MX-1-DL-GP  [C603H40]  122.85 79.53 270 top
C1129  SC22U6D3V3MX-1-DL-GP  [C603H40]  125.98 80.49 180 top
C1130  SC22U6D3V3MX-1-DL-GP  [C603H40]  92.58 35.83 0 bottom
C1131  SC22U6D3V3MX-1-DL-GP  [C603H40]  91.31 33.42 180 bottom
C1132  SC22U6D3V3MX-1-DL-GP  [C603H40]  129.79 47.52 90 bottom
C1133  SC22U6D3V3MX-1-DL-GP  [C603H40]  110.36 74.31 0 top
C1134  SC22U6D3V3MX-1-DL-GP  [C603H40]  148.21 64.41 180 bottom
C1135  SC22U6D3V3MX-1-DL-GP  [C603H40]  120.59 74.75 90 top
C1136  SC10U6D3V3MX-DL-GP  [C603H36]  124.08 47.64 270 bottom
C1137  SC10U6D3V3MX-DL-GP  [C603H36]  144.53 44.09 270 bottom
C1138  SC10U6D3V3MX-DL-GP  [C603H36]  119 47.64 90 bottom
C1139  SCD1U25V2KX-1-DL-GP  [C402H22]  114.01 71.83 180 top
C1140  SCD1U25V2KX-1-DL-GP  [C402H22]  118.53 71.6 180 top
C1141  SCD1U25V2KX-1-DL-GP  [C402H22]  107.08 39.91 0 top
C1142  SCD1U25V2KX-1-DL-GP  [C402H22]  119.45 54.99 90 top
C1201  SCD047U25V2KX-4-GP  [C402H22]  79.45 36.09 90 top
C1202  SCD022U16V2KX-3DLGP  [C402H22]  94.15 34.19 270 top
C1203  SCD047U25V2KX-4-GP  [C402H22]  60.37 36.35 180 top
C1204  SC1U10V2KX-1DLGP  [C402H22]  56.56 46.08 180 top
C1205  SC1U10V2KX-1DLGP  [C402H22]  51.32 45.64 90 top
C1206  SC1U10V2KX-1DLGP  [C402H22]  50.71 44.12 0 top
C1207  SC1U10V2KX-1DLGP  [C402H22]  52.8 40.16 270 top
C1208  SC1U10V2KX-1DLGP  [C402H22]  59.44 33.8 0 top
C1209  SC1U10V2KX-1DLGP  [C402H22]  57.93 42.57 270 top
C1210  SC1U10V2KX-1DLGP  [C402H22]  50.97 40.03 270 top
C1211  SC1U10V2KX-1DLGP  [C402H22]  59.14 38.13 90 top
C1212  SC1U10V2KX-1DLGP  [C402H22]  60.21 44.12 0 top
C1213  SC1U10V2KX-1DLGP  [C402H22]  60.82 45.64 90 top
C1214  SC1U10V2KX-1DLGP  [C402H22]  66.71 46.08 180 top
C1215  SC1U10V2KX-1DLGP  [C402H22]  62.95 40.16 270 top
C1216  SC1U10V2KX-1DLGP  [C402H22]  69.55 33.81 0 top
C1217  SC1U10V2KX-1DLGP  [C402H22]  69.17 38.25 90 top
C1218  SC1U10V2KX-1DLGP  [C402H22]  60.69 38.2 270 top
C1219  SC1U10V2KX-1DLGP  [C402H22]  68.08 42.57 270 top
C1220  SC1U10V2KX-1DLGP  [C402H22]  80.51 44.15 0 top
C1221  SC1U10V2KX-1DLGP  [C402H22]  81.77 45.64 90 top
C1222  SC1U10V2KX-1DLGP  [C402H22]  87.01 46.08 180 top
C1223  SC1U10V2KX-1DLGP  [C402H22]  82.34 33.81 180 top
C1224  SC1U10V2KX-1DLGP  [C402H22]  90.09 41.17 90 top
C1225  SC1U10V2KX-1DLGP  [C402H22]  83.25 40.16 270 top
C1226  SC1U10V2KX-1DLGP  [C402H22]  88.38 42.57 270 top
C1227  SC1U10V2KX-1DLGP  [C402H22]  80.94 38.25 270 top
C1228  SC1U10V2KX-1DLGP  [C402H22]  76.86 46.08 180 top
C1229  SC1U10V2KX-1DLGP  [C402H22]  78.23 42.57 270 top
C1230  SC1U10V2KX-1DLGP  [C402H22]  79.32 38.25 90 top
C1231  SC1U10V2KX-1DLGP  [C402H22]  73.1 40.16 270 top
C1232  SC1U10V2KX-1DLGP  [C402H22]  81.07 35.59 90 top
C1233  SC1U10V2KX-1DLGP  [C402H22]  70.8 38.25 270 top
C1234  SC1U10V2KX-1DLGP  [C402H22]  70.97 45.64 90 top
C1235  SC1U10V2KX-1DLGP  [C402H22]  70.36 44.12 0 top
C1236  SCD047U25V2KX-4-GP  [C402H22]  70.53 36.35 180 top
C1237  SC10U6D3V3MX-DL-GP  [C603H36]  58.72 48.67 180 top
C1238  SC10U6D3V3MX-DL-GP  [C603H36]  96.77 33.29 270 bottom
C1239  SC10U6D3V3MX-DL-GP  [C603H36]  76.71 47.64 90 bottom
C1240  SC10U6D3V3MX-DL-GP  [C603H36]  59.99 48.67 180 top
C1241  SC10U6D3V3MX-DL-GP  [C603H36]  83.57 47.64 270 bottom
C1242  SC10U6D3V3MX-DL-GP  [C603H36]  80.69 48.54 180 top
C1243  SC10U6D3V3MX-DL-GP  [C603H36]  79.42 48.54 180 top
C1244  SC10U6D3V3MX-DL-GP  [C603H36]  74.3 47.64 270 bottom
C1245  SC10U6D3V3MX-DL-GP  [C603H36]  68.33 47.52 90 bottom
C1246  SC10U6D3V3MX-DL-GP  [C603H36]  62.74 47.77 270 bottom
C1247  SCD01U50V2KX-1DLGP  [C402H22]  47.88 41.42 90 top
C1255  SC1U10V2KX-1DLGP  [C402H22]  43.69 30.37 0 top
C1257  SC1U10V2KX-1DLGP  [C402H22]  46.74 41.29 180 top
C1258  SC1U10V2KX-1DLGP  [C402H22]  45.97 30.37 0 top
C1259  SC1U10V2KX-1DLGP  [C402H22]  88.41 44.06 270 top
C1260  SC1U10V2KX-1DLGP  [C402H22]  81.96 30.63 180 bottom
C1261  SC1U10V2KX-1DLGP  [C402H22]  77.22 30.37 180 bottom
C1262  SC1U10V2KX-1DLGP  [C402H22]  68.11 44.06 270 top
C1263  SC1U10V2KX-1DLGP  [C402H22]  61.51 30.38 180 bottom
C1264  SC1U10V2KX-1DLGP  [C402H22]  60.75 30.38 180 bottom
C1265  SC1U10V2KX-1DLGP  [C402H22]  57.96 44.06 270 top
C1266  SC1U10V2KX-1DLGP  [C402H22]  51.69 30.24 180 bottom
C1267  SC1U10V2KX-1DLGP  [C402H22]  50.93 30.24 180 bottom
C1268  SC1U10V2KX-1DLGP  [C402H22]  78.26 44.06 270 top
C1269  SC1U10V2KX-1DLGP  [C402H22]  71.8 30.38 180 bottom
C1270  SC1U10V2KX-1DLGP  [C402H22]  71.04 30.38 180 bottom
C1271  SC1U10V2KX-1DLGP  [C402H22]  85.09 50.06 0 bottom
C1272  SC1U10V2KX-1DLGP  [C402H22]  66.34 49.94 0 bottom
C1273  SC1U10V2KX-1DLGP  [C402H22]  63.16 49.94 0 bottom
C1274  SC1U10V2KX-1DLGP  [C402H22]  79.42 48.54 0 bottom
C1275  SC10U6D3V3MX-DL-GP  [C603H36]  133.99 29.61 180 bottom
C1276  SC10U6D3V3MX-DL-GP  [C603H36]  86.23 50.06 0 bottom
C1277  SC10U6D3V3MX-DL-GP  [C603H36]  70.99 49.55 0 bottom
C1278  SC10U6D3V3MX-DL-GP  [C603H36]  60.07 48.66 0 bottom
C1279  SC10U6D3V3MX-DL-GP  [C603H36]  80.43 48.67 0 bottom
C1280  SC1U10V2KX-1DLGP  [C402H22]  42.72 34.57 270 top
C1281  SC1U10V2KX-1DLGP  [C402H22]  42.72 33.81 270 top
C1282  SC1U10V2KX-1DLGP  [C402H22]  48.77 30.37 0 top
C1283  SC1U10V2KX-1DLGP  [C402H22]  42.72 31.52 270 top
C1284  SC1U10V2KX-1DLGP  [C402H22]  48.01 30.37 0 top
C1285  SC3300P50V2KX-1DLGP  [C402H22]  84.05 37.61 270 top
C1286  SCD047U25V2KX-4-GP  [C402H22]  91.86 35.46 180 top
C1288  SC10U6D3V3MX-DL-GP  [C603H36]  46.43 39.87 270 bottom
C1289  SC10U6D3V3MX-DL-GP  [C603H36]  50.44 28.14 270 bottom
C1290  SC10U6D3V3MX-DL-GP  [C603H36]  48.13 29.48 0 bottom
C1291  SC10U6D3V3MX-DL-GP  [C603H36]  46.43 41.14 270 bottom
C1292  SC1U10V2KX-1DLGP  [C402H22]  42.72 36.09 270 top
C1293  SC1U10V2KX-1DLGP  [C402H22]  45.21 30.37 0 top
C1294  SC1U10V2KX-1DLGP  [C402H22]  42.72 35.33 270 top
C1295  SC1U10V2KX-1DLGP  [C402H22]  44.45 30.37 0 top
C1296  SC1U10V2KX-1DLGP  [C402H22]  42.72 33.05 270 top
C1297  SC1U10V2KX-1DLGP  [C402H22]  42.72 32.28 270 top
C1298  SC1U10V2KX-1DLGP  [C402H22]  42.72 37.62 270 top
C1299  SC1U10V2KX-1DLGP  [C402H22]  42.72 36.86 270 top
C1301  SCD047U25V2KX-4-GP  [C402H22]  140.16 36.62 180 top
C1302  SCD022U16V2KX-3DLGP  [C402H22]  99.34 34.87 90 top
C1303  SCD047U25V2KX-4-GP  [C402H22]  131.49 35.71 0 top
C1304  SC1U10V2KX-1DLGP  [C402H22]  140.86 42.57 270 top
C1305  SC1U10V2KX-1DLGP  [C402H22]  139.06 45.72 90 top
C1306  SC1U10V2KX-1DLGP  [C402H22]  134.26 45.64 90 top
C1307  SC1U10V2KX-1DLGP  [C402H22]  133.65 44.12 0 top
C1308  SC1U10V2KX-1DLGP  [C402H22]  133.9 39.65 270 top
C1309  SC1U10V2KX-1DLGP  [C402H22]  138.1 32.78 0 top
C1310  SC1U10V2KX-1DLGP  [C402H22]  142.08 38.13 90 top
C1311  SC1U10V2KX-1DLGP  [C402H22]  141.65 39.65 90 top
C1312  SC1U10V2KX-1DLGP  [C402H22]  121.78 38.13 90 top
C1313  SC1U10V2KX-1DLGP  [C402H22]  120.56 42.57 270 top
C1314  SC1U10V2KX-1DLGP  [C402H22]  115.43 40.16 270 top
C1315  SC1U10V2KX-1DLGP  [C402H22]  119.19 46.08 180 top
C1316  SC1U10V2KX-1DLGP  [C402H22]  113.71 45.64 90 top
C1317  SC1U10V2KX-1DLGP  [C402H22]  113.35 44.12 0 top
C1318  SC1U10V2KX-1DLGP  [C402H22]  122.04 33.81 0 top
C1319  SC1U10V2KX-1DLGP  [C402H22]  113.83 38.2 270 top
C1320  SC1U10V2KX-1DLGP  [C402H22]  123.5 44.09 0 top
C1321  SC1U10V2KX-1DLGP  [C402H22]  124.11 45.62 90 top
C1322  SC1U10V2KX-1DLGP  [C402H22]  125.58 40.13 270 top
C1323  SC1U10V2KX-1DLGP  [C402H22]  132.19 33.78 0 top
C1324  SC1U10V2KX-1DLGP  [C402H22]  131.93 38.1 90 top
C1325  SC1U10V2KX-1DLGP  [C402H22]  130.71 42.55 270 top
C1326  SC1U10V2KX-1DLGP  [C402H22]  123.98 38.18 270 top
C1327  SC1U10V2KX-1DLGP  [C402H22]  129.34 46.05 180 top
C1328  SC1U10V2KX-1DLGP  [C402H22]  106.81 47.64 270 top
C1329  SC1U10V2KX-1DLGP  [C402H22]  105.07 40.28 270 top
C1330  SC1U10V2KX-1DLGP  [C402H22]  110.39 42.57 270 top
C1331  SC1U10V2KX-1DLGP  [C402H22]  109.02 46.08 180 top
C1332  SC1U10V2KX-1DLGP  [C402H22]  111.6 38.13 90 top
C1333  SC1U10V2KX-1DLGP  [C402H22]  103.76 42.56 270 top
C1334  SC1U10V2KX-1DLGP  [C402H22]  109.14 39.65 0 top
C1335  SC1U10V2KX-1DLGP  [C402H22]  115.44 33.6 90 top
C1336  SCD047U25V2KX-4-GP  [C402H22]  121.53 35.64 0 top
C1337  SC1U10V2KX-1DLGP  [C402H22]  110.54 44.07 270 top
C1338  SC1U10V2KX-1DLGP  [C402H22]  100.88 32.66 90 bottom
C1339  SC1U10V2KX-1DLGP  [C402H22]  113.07 50.7 0 bottom
C1340  SC1U10V2KX-1DLGP  [C402H22]  100.88 33.43 90 bottom
C1341  SC1U10V2KX-1DLGP  [C402H22]  120.69 44.04 270 top
C1342  SC1U10V2KX-1DLGP  [C402H22]  101.98 30.37 180 bottom
C1343  SCD047U25V2KX-4-GP  [C402H22]  111.17 34.19 270 top
C1344  SC1U10V2KX-1DLGP  [C402H22]  123.11 49.3 0 bottom
C1345  SC1U10V2KX-1DLGP  [C402H22]  124.59 30.5 180 bottom
C1346  SC1U10V2KX-1DLGP  [C402H22]  130.71 44.04 270 top
C1347  SC1U10V2KX-1DLGP  [C402H22]  123.74 30.51 180 bottom
C1348  SC1U10V2KX-1DLGP  [C402H22]  122.98 30.51 180 bottom
C1349  SC1U10V2KX-1DLGP  [C402H22]  127 48.53 0 bottom
C1350  SC1U10V2KX-1DLGP  [C402H22]  131.44 29.61 180 bottom
C1351  SC1U10V2KX-1DLGP  [C402H22]  140.94 44.09 270 top
C1352  SC1U10V2KX-1DLGP  [C402H22]  132.97 29.61 180 bottom
C1353  SC1U10V2KX-1DLGP  [C402H22]  141.9 48.54 0 bottom
C1354  SC1U10V2KX-1DLGP  [C402H22]  142.24 30.63 180 bottom
C1355  SC1U10V2KX-1DLGP  [C402H22]  144.27 30.63 180 bottom
C1356  SC1U10V2KX-1DLGP  [C402H22]  147.45 37.99 270 bottom
C1357  SC1U10V2KX-1DLGP  [C402H22]  144.15 36.59 270 top
C1358  SC1U10V2KX-1DLGP  [C402H22]  145.92 31.01 0 top
C1359  SC1U10V2KX-1DLGP  [C402H22]  148.08 39.39 270 bottom
C1360  SC1U10V2KX-1DLGP  [C402H22]  146.69 42.18 0 bottom
C1361  SC1U10V2KX-1DLGP  [C402H22]  146.56 41.42 180 top
C1362  SC1U10V2KX-1DLGP  [C402H22]  145.8 41.42 180 top
C1363  SC1U10V2KX-1DLGP  [C402H22]  145.03 41.42 180 top
C1364  SC1U10V2KX-1DLGP  [C402H22]  147.32 41.42 180 top
C1365  SC1U10V2KX-1DLGP  [C402H22]  144.02 39.39 270 top
C1366  SC1U10V2KX-1DLGP  [C402H22]  148.08 41.42 180 top
C1367  SC1U10V2KX-1DLGP  [C402H22]  148.84 41.42 180 top
C1368  SC1U10V2KX-1DLGP  [C402H22]  145.16 31.01 0 top
C1369  SC1U10V2KX-1DLGP  [C402H22]  144.4 31.01 0 top
C1370  SCD01U50V2KX-1DLGP  [C402H22]  145.41 42.69 90 bottom
C1371  SC10U6D3V3MX-DL-GP  [C603H36]  112.06 50.57 0 bottom
C1372  SC10U6D3V3MX-DL-GP  [C603H36]  135.25 29.61 180 bottom
C1373  SC10U6D3V3MX-DL-GP  [C603H36]  122.09 49.3 0 bottom
C1374  SC10U6D3V3MX-DL-GP  [C603H36]  124.97 49.55 0 bottom
C1375  SC10U6D3V3MX-DL-GP  [C603H36]  140.89 48.67 0 bottom
C1376  SC10U6D3V3MX-DL-GP  [C603H36]  148.31 41.7 270 bottom
C1377  SC10U6D3V3MX-DL-GP  [C603H36]  148.31 40.43 270 bottom
C1378  SC10U6D3V3MX-DL-GP  [C603H36]  146.56 30.75 180 bottom
C1379  SC10U6D3V3MX-DL-GP  [C603H36]  145.29 30.75 180 bottom
C1388  SC3300P50V2KX-1DLGP  [C402H22]  105.98 37.63 270 top
C1390  SC10U6D3V3MX-DL-GP  [C603H36]  92.58 33.42 180 bottom
C1391  SC10U6D3V3MX-DL-GP  [C603H36]  49.66 43.2 0 bottom
C1392  SC10U6D3V3MX-DL-GP  [C603H36]  114.17 47.64 270 bottom
C1393  SC10U6D3V3MX-DL-GP  [C603H36]  144.53 45.36 270 bottom
C1394  SC10U6D3V3MX-DL-GP  [C603H36]  49.02 41.29 90 bottom
C1395  SC10U6D3V3MX-DL-GP  [C603H36]  96.77 32.02 270 bottom
C1396  SC10U6D3V3MX-DL-GP  [C603H36]  96.72 35.27 270 bottom
C1397  SC10U6D3V3MX-DL-GP  [C603H36]  91.19 39.64 180 bottom
C1398  SC10U6D3V3MX-DL-GP  [C603H36]  86.74 47.64 90 bottom
C1399  SC10U6D3V3MX-DL-GP  [C603H36]  110.36 47.64 90 bottom
C1701  SC220P50V2KX-3DLGP  [C402H22]  136.63 55.26 270 top
C1710  SCD47U10V2KX-1-GP  [C402H22]  148.72 51.96 270 bottom
C1711  SCD022U16V2KX-3DLGP  [C402H22]  156.84 80.66 180 bottom
C1803  SC15P50V2JN-DL-GP  [C402H22]  124.45 57.53 90 top
C1804  SC15P50V2JN-DL-GP  [C402H22]  122.93 57.53 270 top
C1805  SC1U10V2KX-1DLGP  [C402H22]  137.61 49.4 180 bottom
C1806  SC1U10V2KX-1DLGP  [C402H22]  135.48 51.66 0 bottom
C1807  SC15P50V2JN-DL-GP  [C402H22]  136.02 95.9 270 bottom
C1808  SC15P50V2JN-DL-GP  [C402H22]  134.49 95.9 90 bottom
C2201  SCD1U16V2KX-3DLGP  [C402H22]  123.03 76.25 0 top
C2202  SC1U10V2KX-1DLGP  [C402H22]  129.53 77.88 180 top
C2203  SC1U10V2KX-1DLGP  [C402H22]  132.66 74.4 0 top
C2204  SC1U10V2KX-1DLGP  [C402H22]  133.91 74.44 0 top
C2205  SC1U10V2KX-1DLGP  [C402H22]  134.69 74.45 0 top
C2206  SCD1U25V2KX-1-DL-GP  [C402H22]  135.45 74.45 0 top
C2207  SCD1U25V2KX-1-DL-GP  [C402H22]  135.13 73.3 270 top
C2208  SC22U6D3V3MX-1-DL-GP  [C603H40]  124.88 97.18 90 bottom
C2209  SC1U10V2KX-1DLGP  [C402H22]  124.63 96.16 90 bottom
C2210  SC1U10V2KX-1DLGP  [C402H22]  128.95 80.87 270 top
C2211  SC1U10V2KX-1DLGP  [C402H22]  130.12 81.48 180 top
C2212  SC1U10V2KX-1DLGP  [C402H22]  129.41 82.63 90 top
C2213  SC1U10V2KX-1DLGP  [C402H22]  126.67 75.94 90 top
C2214  SC1U10V2KX-1DLGP  [C402H22]  170.05 72.92 180 top
C2215  SC1U10V2KX-1DLGP  [C402H22]  170.81 72.92 180 top
C2216  SC1U10V2KX-1DLGP  [C402H22]  152.65 81.17 180 top
C2217  SC1U10V2KX-1DLGP  [C402H22]  166.37 66.19 180 bottom
C2218  SC4D7U6D3V3KX-DLGP  [C603H36]  137.41 74.06 270 top
C2219  SC1U10V2KX-1DLGP  [C402H22]  140.84 97.3 0 bottom
C2220  SC22U6D3V3MX-1-DL-GP  [C603H40]  153.54 80.54 0 bottom
C2221  SCD1U25V2KX-1-DL-GP  [C402H22]  148.97 60.72 270 top
C2222  SC1U10V2KX-1DLGP  [C402H22]  148.97 61.61 270 top
C2223  SC1U10V2KX-1DLGP  [C402H22]  122.34 78.13 180 top
C2224  SC1U10V2KX-1DLGP  [C402H22]  147.45 60.72 90 top
C2405  SC100P50V2JN-3DLGP  [C402H22]  102.74 10.43 90 bottom
C2406  SCD1U25V2KX-1-DL-GP  [C402H22]  102.74 9.67 90 bottom
C2407  SCD1U25V2KX-1-DL-GP  [C402H22]  94.61 7 270 top
C2408  SCD1U25V2KX-1-DL-GP  [C402H22]  92.94 7 90 top
C2409  SCD01U50V2KX-1DLGP  [C402H22]  83.57 18.18 180 top
C2410  SCD1U25V2KX-1-DL-GP  [C402H22]  83.82 15.39 90 top
C2411  SCD1U25V2KX-1-DL-GP  [C402H22]  90.04 19.07 90 top
C2412  SCD1U25V2KX-1-DL-GP  [C402H22]  95.38 8.78 90 top
C2413  SCD1U25V2KX-1-DL-GP  [C402H22]  89.28 6.62 0 top
C2414  SCD1U25V2KX-1-DL-GP  [C402H22]  98.5 19.45 270 top
C2416  SCD1U25V2KX-1-DL-GP  [C402H22]  78.99 17.29 270 top
C2418  SC1U10V2KX-1DLGP  [C402H22]  83.82 14.5 270 top
C2420  SCD1U25V2KX-1-DL-GP  [C402H22]  97.94 11.45 270 top
C2421  SCD1U25V2KX-1-DL-GP  [C402H22]  78.99 16.53 270 top
C2422  SCD1U25V2KX-1-DL-GP  [C402H22]  93.85 8.78 270 top
C2423  SCD1U25V2KX-1-DL-GP  [C402H22]  91.19 19.45 0 top
C2424  SC18P50V2JN-1DLGP  [C402H22]  86.23 4.84 270 bottom
C2425  SC18P50V2JN-1DLGP  [C402H22]  86.49 3.57 180 bottom
C2427  SC2D2U10V3KX-1DLGP-U  [C603H36]  81.74 6.83 90 bottom
C2428  SCD1U25V2KX-1-DL-GP  [C402H22]  86.36 6.24 270 top
C2429  SCD1U25V2KX-1-DL-GP  [C402H22]  83.82 16.15 90 top
C2435  SC2200P50V2KX-2DLGP  [C402H22]  91.19 6.11 270 top
C2441  SC2200P50V2KX-2DLGP  [C402H22]  91.19 7 90 top
C2501  SC10U6D3V3MX-DL-GP  [C603H36]  138.18 60.6 180 bottom
C2502  SCD1U16V2KX-3DLGP  [C402H22]  139.19 60.47 180 bottom
C2503  SCD47U10V2KX-1-GP  [C402H22]  156.34 77.72 0 bottom
C2517  SCD022U16V2KX-3DLGP  [C402H22]  161.04 50.36 180 bottom
C2525  SC1U10V2KX-1DLGP  [C402H22]  158.24 71.14 270 bottom
C2601  SC10U6D3V3MX-DL-GP  [C603H36]  32.64 15.39 270 bottom
C2602  SCD1U25V2KX-1-DL-GP  [C402H22]  149.81 46.42 270 top
C2603  SC2200P50V2KX-2DLGP  [C402H22]  171.45 82.97 0 bottom
C2604  SC4D7U6D3V3KX-DLGP  [C603H36]  171.32 81.3 270 bottom
C2605  SCD1U25V2KX-1-DL-GP  [C402H22]  170.64 82.97 0 bottom
C2606  SC470P50V2KX-3DLGP  [C402H22]  48.77 66.69 90 bottom
C2607  SC2200P50V2KX-2DLGP  [C402H22]  151.99 41.62 90 bottom
C2608  SCD1U16V2KX-3DLGP  [C402H22]  43.26 13.07 270 bottom
C2609  SCD1U16V2KX-3DLGP  [C402H22]  43.26 13.84 270 bottom
C2610  SCD1U16V2KX-3DLGP  [C402H22]  148.46 98.95 270 top
C2612  SCD1U25V2KX-1-DL-GP  [C402H22]  64.01 55.39 270 bottom
C2613  SC100P50V2JN-3DLGP  [C402H22]  93.34 2.43 0 top
C2614  SCD1U16V2KX-3DLGP  [C402H22]  149.61 95.65 90 top
C2714  SCD1U25V2KX-1-DL-GP  [C402H22]  26.16 14.37 90 top
C2721  SCD1U25V2KX-1-DL-GP  [C402H22]  20.7 13.1 270 top
C2722  SCD1U25V2KX-1-DL-GP  [C402H22]  29.08 16.02 0 top
C2726  SCD1U25V2KX-1-DL-GP  [C402H22]  17.53 16.66 90 top
C2727  SC10U6D3V3MX-DL-GP  [C603H36]  20.95 12.34 180 bottom
C2729  SCD1U25V2KX-1-DL-GP  [C402H22]  29.84 16.02 0 top
C2730  SC10U6D3V3MX-DL-GP  [C603H36]  22.23 23.64 90 bottom
C2731  SC10U6D3V2MX-2-GP  [C402-TO0D2H28]  19.68 12.34 180 bottom
C2732  SC10U6D3V3MX-DL-GP  [C603H36]  22.99 11.32 180 bottom
C2733  SC10U6D3V3MX-DL-GP  [C603H36]  25.15 11.32 180 bottom
C2734  SC10U6D3V2MX-2-GP  [C402-TO0D2H28]  21.72 21.48 90 bottom
C2735  SC10U6D3V2MX-2-GP  [C402-TO0D2H28]  20.7 19.96 0 bottom
C2736  SC10U6D3V2MX-2-GP  [C402-TO0D2H28]  23.5 21.1 180 bottom
C2737  SC2D2U10V3KX-1DLGP-U  [C603H36]  19.81 14.75 0 bottom
C2738  SC10P50V2JN-4DLGP  [C402H22]  29.46 18.94 270 top
C2739  SC1U25V3KX-1-DLGP  [C603H36]  19.81 23.13 0 bottom
C2740  SCD1U25V2KX-1-DL-GP  [C402H22]  22.35 23.64 270 top
C2741  SC1U25V3KX-1-DLGP  [C603H36]  18.54 23.13 0 bottom
C2742  SCD1U25V2KX-1-DL-GP  [C402H22]  24 11.19 180 bottom
C2743  SC10U6D3V2MX-2-GP  [C402-TO0D2H28]  25.4 16.78 90 bottom
C2744  SCD1U25V2KX-1-DL-GP  [C402H22]  24.26 25.29 90 top
C2745  SC10U6D3V3MX-DL-GP  [C603H36]  24.64 20.97 180 bottom
C2746  SCD1U16V2KX-3DLGP  [C402H22]  29.59 13.99 90 top
C2907  SC10U6D3V3MX-DL-GP  [C603H36]  17.55 17.93 0 bottom
C2908  SC10U6D3V3MX-DL-GP  [C603H36]  18.82 17.93 0 bottom
C2909  SC10U6D3V3MX-DL-GP  [C603H36]  24.05 15.64 90 bottom
C3401  SC1U10V2KX-1DLGP  [C402H22]  19.18 44.47 90 top
C3402  SCD1U25V2KX-1-DL-GP  [C402H22]  21.59 43.96 270 top
C3403  SCD1U25V2KX-1-DL-GP  [C402H22]  19.18 45.23 90 top
C3404  SC22U6D3V3MX-1-DL-GP  [C603H40]  18.14 46.47 0 bottom
C3405  SC22U6D3V3MX-1-DL-GP  [C603H40]  19.3 46.47 0 bottom
C3501  SCD1U25V2KX-1-DL-GP  [C402H22]  22.73 40.79 270 top
C3502  SCD1U25V2KX-1-DL-GP  [C402H22]  22.73 41.55 270 top
C4001  SC470P50V2KX-3DLGP  [C402H22]  106.05 27.96 180 bottom
C4002  SC470P50V2KX-3DLGP  [C402H22]  105.28 27.96 180 bottom
C4003  SCD22U10V2KX-2-GP  [C402H22]  106.17 21.1 180 bottom
C4004  SC10U25V5KX-DL-GP  [C805H58]  103 25.55 180 bottom
C4005  SC10U25V5KX-DL-GP  [C805H58]  110.24 26.82 270 bottom
C4006  SC10U6D3V3MX-DL-GP  [C603H36]  150.24 63.26 0 bottom
C4007  SCD1U16V2KX-3DLGP  [C402H22]  152.2 59.45 270 bottom
C4008  SC10U6D3V3MX-DL-GP  [C603H36]  149.52 68.73 90 bottom
C4009  SC10U6D3V3MX-DL-GP  [C603H36]  101.22 19.83 270 bottom
C4010  SCD1U25V2KX-1-DL-GP  [C402H22]  160.66 64.92 270 bottom
C4012  SC10U6D3V3MX-DL-GP  [C603H36]  151.51 98.19 180 bottom
C4013  SC10U6D3V3MX-DL-GP  [C603H36]  147.96 94.25 90 bottom
C4031  SC1U10V2KX-1DLGP  [C402H22]  149.61 94.89 90 top
C4032  SC1U10V2KX-1DLGP  [C402H22]  160.66 70.25 0 bottom
C4034  SCD1U25V2KX-1-DL-GP  [C402H22]  149.61 94.13 90 top
C4035  SC1U10V2KX-1DLGP  [C402H22]  149.22 63.77 0 bottom
C4037  SCD1U25V2KX-1-DL-GP  [C402H22]  32.26 20.47 180 bottom
C4038  SC1U10V2KX-1DLGP  [C402H22]  31.19 22.47 90 bottom
C4039  SCD1U16V2KX-3DLGP  [C402H22]  32.38 18.05 90 top
C4040  SCD1U25V2KX-1-DL-GP  [C402H22]  154.81 61 180 bottom
C4041  SC22U6D3V3MX-1-DL-GP  [C603H40]  149.52 70 90 bottom
C4042  SC22U6D3V3MX-1-DL-GP  [C603H40]  149.52 67.46 90 bottom
C4043  SC1U10V2KX-1DLGP  [C402H22]  158.62 69.91 0 bottom
C4301  SC1U50V3KX-1-GP  [C603H36]  34.16 77.62 270 bottom
C4302  SCD1U50V3KX-DL-GP  [C603H35]  31.24 77.74 0 bottom
C4303  SCD01U50V2KX-1DLGP  [C402H22]  35.18 72.54 270 bottom
C4304  SCD01U50V2KX-1DLGP  [C402H22]  35.18 71.77 270 bottom
C4305  SCD01U50V2KX-1DLGP  [C402H22]  35.18 71.01 270 bottom
C4306  SC10U25V5KX-DL-GP  [C805H58]  29.08 70.88 90 bottom
C4343  SC1500P50V2KX-2-DL-GP  [C402H22]  28.65 28.69 0 bottom
C4344  SC1KP50V2KX-1DLGP  [C402H22]  33.22 59.78 270 top
C5501  SCD1U25V2KX-1-DL-GP  [C402H22]  94.61 103.9 180 top
C5502  SC4D7U6D3V3KX-DLGP  [C603H36]  123.57 106.19 0 bottom
C5503  SC4D7U6D3V3KX-DLGP  [C603H36]  105.03 103.4 180 top
C5504  SCD1U25V2KX-1-DL-GP  [C402H22]  95.38 103.9 180 top
C5505  SC22U6D3V3MX-1-DL-GP  [C603H40]  118.62 102 180 bottom
C5506  SCD1U25V2KX-1-DL-GP  [C402H22]  96.52 103.9 180 top
C5507  SCD1U25V2KX-1-DL-GP  [C402H22]  103 101.75 90 top
C5508  SC1U10V2KX-1DLGP  [C402H22]  103 102.51 90 top
C5509  SCD1U25V2KX-1-DL-GP  [C402H22]  97.28 103.9 180 top
C5510  SCD1U25V2KX-1-DL-GP  [C402H22]  88.9 103.9 180 top
C5511  SCD1U25V2KX-1-DL-GP  [C402H22]  89.66 103.9 180 top
C5512  SCD1U50V3KX-DL-GP  [C603H35]  75.69 97.05 0 bottom
C5513  SC1KP50V2KX-1DLGP  [C402H22]  85.09 97.22 180 bottom
C5514  SC10U25V5KX-DL-GP  [C805H58]  75.44 94.38 180 bottom
C5515  SC4D7U6D3V3KX-DLGP  [C603H36]  57.02 93.24 0 bottom
C5516  SCD1U50V3KX-DL-GP  [C603H35]  75.31 89.65 270 bottom
C5517  SC10U6D3V3MX-DL-GP  [C603H36]  75.31 92.19 270 bottom
C5518  SC10U6D3V3MX-DL-GP  [C603H36]  75.31 90.92 270 bottom
C5519  SCD1U25V2KX-1-DL-GP  [C402H22]  93.34 103.9 180 top
C5521  SCD1U50V3KX-DL-GP  [C603H35]  114.55 97.3 270 bottom
C5522  SC1KP50V2KX-1DLGP  [C402H22]  112.01 101.36 90 top
C5531  SCD1U25V2KX-1-DL-GP  [C402H22]  91.44 103.9 180 top
C5532  SCD1U25V2KX-1-DL-GP  [C402H22]  90.68 103.9 180 top
C5533  SCD1U25V2KX-1-DL-GP  [C402H22]  92.58 103.9 180 top
C5535  SC1U10V2KX-1DLGP  [C402H22]  50.55 89.12 270 top
C5701  SC2D2U10V2KX-GP  [C402H22]  29.34 51.96 0 top
C5724  SCD75P50V1CN-GP  [C0201H13]  24.92 57.42 270 top
C5725  SC1U10V2KX-1DLGP  [C402H22]  29.84 57.42 90 bottom
C5726  SCD1U25V2KX-1-DL-GP  [C402H22]  21.21 48.66 180 bottom
C5727  SCD1U25V2KX-1-DL-GP  [C402H22]  28.69 68.41 0 top
C5728  SCD1U25V2KX-1-DL-GP  [C402H22]  29.45 68.41 0 top
C5729  SC20P50V2JN-1-DL-GP  [C402H22]  32 55.14 90 bottom
C5730  SC20P50V2JN-1-DL-GP  [C402H22]  29.97 55.14 270 bottom
C5731  SCD1U25V2KX-1-DL-GP  [C402H22]  31.48 68.41 0 top
C5732  SCD1U25V2KX-1-DL-GP  [C402H22]  30.72 69.93 0 top
C5733  SCD1U25V2KX-1-DL-GP  [C402H22]  27.42 69.93 0 top
C5734  SCD1U25V2KX-1-DL-GP  [C402H22]  29.96 69.93 0 top
C5735  SCD1U25V2KX-1-DL-GP  [C402H22]  28.18 69.93 0 top
C5736  SCD1U25V2KX-1-DL-GP  [C402H22]  14.43 64.92 180 bottom
C5737  SCD1U25V2KX-1-DL-GP  [C402H22]  32.25 68.41 0 top
C5738  SCD1U25V2KX-1-DL-GP  [C402H22]  34.82 70.17 0 top
C5739  SCD1U25V2KX-1-DL-GP  [C402H22]  34.06 70.17 0 top
C5740  SCD1U25V2KX-1-DL-GP  [C402H22]  34.29 66.06 0 top
C5741  SCD1U25V2KX-1-DL-GP  [C402H22]  33.53 66.06 0 top
C5742  SC10U6D3V3MX-DL-GP  [C603H36]  25.93 30.78 180 bottom
C5743  SC1U10V2KX-1DLGP  [C402H22]  22.94 36.47 0 bottom
C5744  SCD1U25V2KX-1-DL-GP  [C402H22]  27.3 30.37 90 bottom
C5745  SC68P50V2JN-1DLGP  [C402H22]  23.83 40.96 180 bottom
C5746  SC10U6D3V3MX-DL-GP  [C603H36]  28.02 41.34 270 bottom
C5747  SC10U6D3V3MX-DL-GP  [C603H36]  27.94 40.15 270 bottom
C5748  SCD47U10V2KX-1-GP  [C402H22]  23.85 45.18 180 bottom
C5749  SC10U6D3V3MX-DL-GP  [C603H36]  27.3 56.15 270 bottom
C5750  SCD1U25V2KX-1-DL-GP  [C402H22]  23.24 64.41 90 bottom
C5751  SCD1U25V2KX-1-DL-GP  [C402H22]  24.51 57.42 90 bottom
C5752  SCD1U25V2KX-1-DL-GP  [C402H22]  24.51 58.18 90 bottom
C5753  SCD47U10V2KX-1-GP  [C402H22]  27.18 42.82 180 bottom
C5754  SC10U6D3V2MX-2-GP  [C402-TO0D2H28]  26.16 48.02 180 top
C5755  SCD1U25V2KX-1-DL-GP  [C402H22]  28.07 60.88 180 bottom
C5756  SCD1U25V2KX-1-DL-GP  [C402H22]  30.23 61.74 270 bottom
C5757  SCD01U50V2KX-1DLGP  [C402H22]  30.23 62.5 270 bottom
C5758  SCD01U50V2KX-1DLGP  [C402H22]  29.97 63.26 270 bottom
C5759  SCD47U10V2KX-1-GP  [C402H22]  27.94 42.82 180 bottom
C5760  SC10U6D3V2MX-2-GP  [C402-TO0D2H28]  26.16 46.12 180 top
C5761  SCD1U25V2KX-1-DL-GP  [C402H22]  24.51 59.71 90 bottom
C5762  SCD01U50V2KX-1DLGP  [C402H22]  24.51 58.95 90 bottom
C5763  SCD47U10V2KX-1-GP  [C402H22]  27.43 47.39 270 top
C5764  SC10U6D3V2MX-2-GP  [C402-TO0D2H28]  27.18 49.29 270 bottom
C5765  SCD1U25V2KX-1-DL-GP  [C402H22]  25.53 64.92 0 bottom
C5766  SCD1U25V2KX-1-DL-GP  [C402H22]  29.97 64.03 270 bottom
C5767  SCD1U25V2KX-1-DL-GP  [C402H22]  28.57 64.92 0 bottom
C5768  SCD01U50V2KX-1DLGP  [C402H22]  27.81 64.92 0 bottom
C5769  SCD01U50V2KX-1DLGP  [C402H22]  27.05 64.92 0 bottom
C5770  SCD01U50V2KX-1DLGP  [C402H22]  26.29 64.92 0 bottom
C5771  SCD47U10V2KX-1-GP  [C402H22]  27.43 46.63 270 top
C5772  SC10U6D3V2MX-2-GP  [C402-TO0D2H28]  26.16 44.21 0 top
C5773  SCD1U25V2KX-1-DL-GP  [C402H22]  28.57 58.06 180 bottom
C5774  SCD1U25V2KX-1-DL-GP  [C402H22]  27.81 58.06 180 bottom
C5775  SCD01U50V2KX-1DLGP  [C402H22]  27.05 58.06 180 bottom
C5776  SCD01U50V2KX-1DLGP  [C402H22]  26.29 58.06 180 bottom
C5777  SCD1U16V2KX-3DLGP  [C402H22]  16.26 57.04 270 bottom
C6101  SCD1U16V2KX-3DLGP  [C402H22]  178 36.59 270 top
C6102  SCD1U16V2KX-3DLGP  [C402H22]  178.66 42.61 180 top
C6103  SCD1U16V2KX-3DLGP  [C402H22]  175.11 32.68 180 top
C6104  SC10U6D3V3MX-DL-GP  [C603H36]  166.88 46.25 270 bottom
C6105  SCD1U25V2KX-1-DL-GP  [C402H22]  178 38.12 270 top
C6106  SCD1U25V2KX-1-DL-GP  [C402H22]  178 37.36 270 top
C6107  SCD1U25V2KX-1-DL-GP  [C402H22]  123.67 93.24 180 bottom
C6108  SCD1U25V2KX-1-DL-GP  [C402H22]  124.46 93.24 180 bottom
C6302  SCD22U10V2KX-2-GP  [C402H22]  167.39 19.58 90 bottom
C6303  SCD22U10V2KX-2-GP  [C402H22]  167.39 20.34 90 bottom
C6304  SC33P50V2JN-3DLGP  [C402H22]  171.45 20.59 270 top
C6305  SC33P50V2JN-3DLGP  [C402H22]  171.45 22.88 270 top
C6306  SCD047U25V2KX-4-GP  [C402H22]  171.45 19.83 270 top
C6307  SCD1U25V2KX-1-DL-GP  [C402H22]  171.45 24.28 270 top
C6308  SCD047U25V2KX-4-GP  [C402H22]  168.15 3.96 0 top
C6311  SCD22U10V2KX-2-GP  [C402H22]  167.13 23.01 0 bottom
C6312  SCD22U10V2KX-2-GP  [C402H22]  167.89 23.01 0 bottom
C6313  SCD22U10V2KX-2-GP  [C402H22]  169.42 25.55 0 bottom
C6314  SCD22U10V2KX-2-GP  [C402H22]  170.18 25.55 0 bottom
C6315  SCD22U10V2KX-2-GP  [C402H22]  171.7 26.69 0 bottom
C6316  SCD22U10V2KX-2-GP  [C402H22]  172.47 26.69 0 bottom
C6317  SC22U6D3V3MX-1-DL-GP  [C603H40]  148.36 10.79 0 bottom
C6318  SC22U6D3V3MX-1-DL-GP  [C603H40]  146.56 10.2 90 bottom
C6401  SCD1U16V2KX-3DLGP  [C402H22]  123.11 7.33 0 bottom
C6501  SCD1U25V2KX-1-DL-GP  [C402H22]  72.52 13.73 270 bottom
C6502  SCD1U25V2KX-1-DL-GP  [C402H22]  128.91 11.7 90 bottom
C6504  SCD1U16V2KX-3DLGP  [C402H22]  76.58 18.31 90 top
C6505  SCD1U25V2KX-1-DL-GP  [C402H22]  133.48 7.89 0 top
C6506  SCD1U16V2KX-3DLGP  [C402H22]  72.52 14.5 270 bottom
C6605  SCD1U16V2KX-3DLGP  [C402H22]  162.84 43.83 180 top
C6701  SCD047U25V2KX-4-GP  [C402H22]  19.43 32.63 270 bottom
C6702  SCD1U25V2KX-1-DL-GP  [C402H22]  184.4 51.58 0 top
C7001  SC10U6D3V3MX-DL-GP  [C603H36]  186.31 41.42 90 top
C7002  SCD1U25V2KX-1-DL-GP  [C402H22]  185.55 42.44 90 top
C7101  SCD1U25V2KX-1-DL-GP  [C402H22]  37.47 85.36 180 bottom
C7102  SCD1U25V2KX-1-DL-GP  [C402H22]  36.7 85.36 180 bottom
C7103  SCD1U16V2KX-3DLGP  [C402H22]  42.67 94.76 90 bottom
C7104  SCD1U16V2KX-3DLGP  [C402H22]  42.67 95.52 90 bottom
C7105  SCD1U16V2KX-3DLGP  [C402H22]  41.15 96.03 90 bottom
C7106  SCD1U16V2KX-3DLGP  [C402H22]  41.15 96.79 90 bottom
C7107  SCD1U16V2KX-3DLGP  [C402H22]  43.56 91.84 90 bottom
C7108  SCD1U16V2KX-3DLGP  [C402H22]  42.04 90.32 90 bottom
C7109  SCD1U16V2KX-3DLGP  [C402H22]  42.04 91.08 90 bottom
C7110  SCD1U16V2KX-3DLGP  [C402H22]  43.56 88.89 90 bottom
C7111  SCD1U16V2KX-3DLGP  [C402H22]  43.56 89.65 90 bottom
C7112  SCD1U16V2KX-3DLGP  [C402H22]  42.04 94 90 bottom
C7113  SCD1U16V2KX-3DLGP  [C402H22]  42.04 93.24 90 bottom
C7114  SCD1U16V2KX-3DLGP  [C402H22]  43.56 92.6 90 bottom
C7115  SCD1U25V2KX-1-DL-GP  [C402H22]  35.18 94.76 180 bottom
C7116  SCD1U25V2KX-1-DL-GP  [C402H22]  36.07 88.92 0 top
C7117  SCD1U25V2KX-1-DL-GP  [C402H22]  39.37 94.89 180 top
C7118  SCD1U25V2KX-1-DL-GP  [C402H22]  40.77 87.39 0 bottom
C7119  SC10U6D3V3MX-DL-GP  [C603H36]  41.78 87.52 180 bottom
C7161  SCD1U25V2KX-1-DL-GP  [C402H22]  18.8 89.17 90 top
C7162  SCD1U25V2KX-1-DL-GP  [C402H22]  18.8 88.41 90 top
C7163  SCD1U25V2KX-1-DL-GP  [C402H22]  19.43 81.93 180 top
C7164  SCD1U25V2KX-1-DL-GP  [C402H22]  20.19 81.93 180 top
C7201  SC2D2U10V2KX-GP  [C402H22]  11.68 80.16 270 bottom
C7202  SC2D2U10V3KX-1DLGP-U  [C603H36]  16.76 73.42 0 bottom
C7203  SC2D2U10V2KX-GP  [C402H22]  11.68 86 270 bottom
C7204  SC22U6D3V3MX-1-DL-GP  [C603H40]  20.83 77.11 90 bottom
